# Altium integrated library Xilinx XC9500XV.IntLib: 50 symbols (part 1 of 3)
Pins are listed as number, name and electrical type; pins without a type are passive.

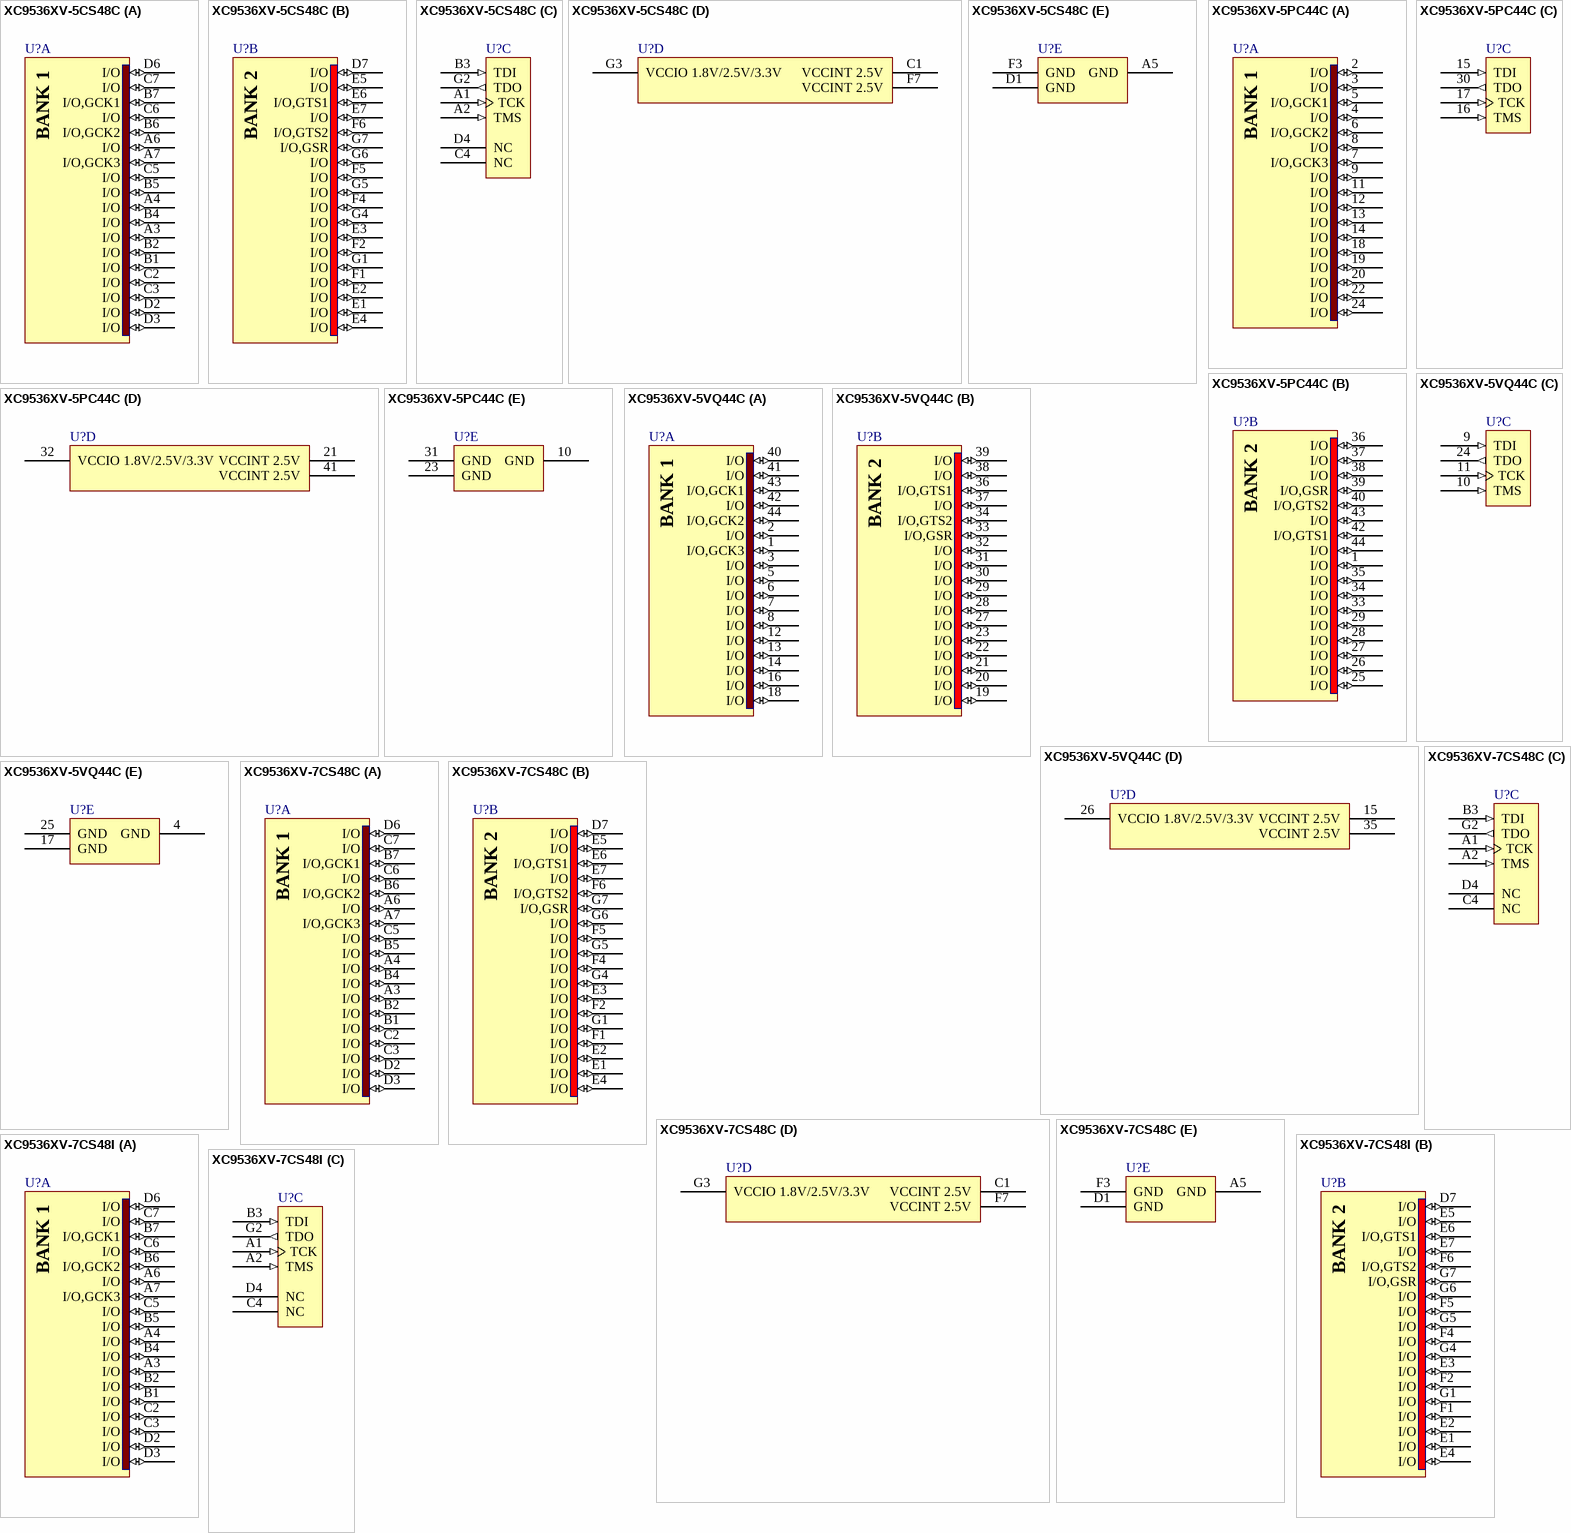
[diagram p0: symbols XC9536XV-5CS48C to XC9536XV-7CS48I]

## XC9536XV-5CS48C
designator U?
XC9500XV, 2.5V High-Performance CPLD with 36 Macrocells, 36 I/Os, 48-Ball CSBGA, Speed Grade 5, Commercial Grade
footprint CS48 (BGA, 48-Leads, Body 7x7mm, Pitch 0.8mm)
signal-integrity model XC9536XV_CS48 (XC9500XV)
part A pins: A3 I/O (io), A4 I/O (io), A6 I/O (io), A7 I/O,GCK3 (io), B1 I/O (io), B2 I/O (io), B4 I/O (io), B5 I/O (io), B6 I/O,GCK2 (io), B7 I/O,GCK1 (io), C2 I/O (io), C3 I/O (io), C5 I/O (io), C6 I/O (io), C7 I/O (io), D2 I/O (io), D3 I/O (io), D6 I/O (io)
part B pins: D7 I/O (io), E1 I/O (io), E2 I/O (io), E3 I/O (io), E4 I/O (io), E5 I/O (io), E6 I/O,GTS1 (io), E7 I/O (io), F1 I/O (io), F2 I/O (io), F4 I/O (io), F5 I/O (io), F6 I/O,GTS2 (io), G1 I/O (io), G4 I/O (io), G5 I/O (io), G6 I/O (io), G7 I/O,GSR (io)
part C pins: A1 TCK (in), A2 TMS (in), B3 TDI (in), C4 NC, D4 NC, G2 TDO (out)
part D pins: C1 VCCINT 2.5V (power), F7 VCCINT 2.5V (power), G3 VCCIO 1.8V/2.5V/3.3V (power)
part E pins: A5 GND (power), D1 GND (power), F3 GND (power)

## XC9536XV-5PC44C
designator U?
XC9500XV, 2.5V High-Performance CPLD with 36 Macrocells, 34 I/Os, 44-Pin PLCC, Speed Grade 5, Commercial Grade
footprint PC44_N (Leaded Chip Carrier, 44-Leads, Body 16.6x16.6mm, Pitch 1.27mm, IPC Medium Density)
footprint PC44_L (Leaded Chip Carrier, 44-Leads, Body 16.6x16.6mm, Pitch 1.27mm, IPC High Density)
footprint PC44_M (Leaded Chip Carrier, 44-Leads, Body 16.6x16.6mm, Pitch 1.27mm, IPC Low Density)
signal-integrity model XC9536XV_PLCC44 (XC9500XV)
part A pins: 2 I/O (io), 3 I/O (io), 4 I/O (io), 5 I/O,GCK1 (io), 6 I/O,GCK2 (io), 7 I/O,GCK3 (io), 8 I/O (io), 9 I/O (io), 11 I/O (io), 12 I/O (io), 13 I/O (io), 14 I/O (io), 18 I/O (io), 19 I/O (io), 20 I/O (io), 22 I/O (io), 24 I/O (io)
part B pins: 1 I/O (io), 25 I/O (io), 26 I/O (io), 27 I/O (io), 28 I/O (io), 29 I/O (io), 33 I/O (io), 34 I/O (io), 35 I/O (io), 36 I/O (io), 37 I/O (io), 38 I/O (io), 39 I/O,GSR (io), 40 I/O,GTS2 (io), 42 I/O,GTS1 (io), 43 I/O (io), 44 I/O (io)
part C pins: 15 TDI (in), 16 TMS (in), 17 TCK (in), 30 TDO (out)
part D pins: 21 VCCINT 2.5V (power), 32 VCCIO 1.8V/2.5V/3.3V (power), 41 VCCINT 2.5V (power)
part E pins: 10 GND (power), 23 GND (power), 31 GND (power)

## XC9536XV-5VQ44C
designator U?
XC9500XV, 2.5V High-Performance 36 Macrocell CPLD, 34 User I/Os, 44-Pin VQFP, Speed Grade 5, Commercial Grade
footprint VQ44_N (Thin QFP, 44-Leads, Body 10x10mm, Pitch 0.8mm, IPC Medium Density)
footprint VQ44_L (Thin QFP, 44-Leads, Body 10x10mm, Pitch 0.8mm, IPC High Density)
footprint VQ44_M (Thin QFP, 44-Leads, Body 10x10mm, Pitch 0.8mm, IPC Low Density)
signal-integrity model XC9536XV_VQ44 (XC9500XV)
part A pins: 1 I/O,GCK3 (io), 2 I/O (io), 3 I/O (io), 5 I/O (io), 6 I/O (io), 7 I/O (io), 8 I/O (io), 12 I/O (io), 13 I/O (io), 14 I/O (io), 16 I/O (io), 18 I/O (io), 40 I/O (io), 41 I/O (io), 42 I/O (io), 43 I/O,GCK1 (io), 44 I/O,GCK2 (io)
part B pins: 19 I/O (io), 20 I/O (io), 21 I/O (io), 22 I/O (io), 23 I/O (io), 27 I/O (io), 28 I/O (io), 29 I/O (io), 30 I/O (io), 31 I/O (io), 32 I/O (io), 33 I/O,GSR (io), 34 I/O,GTS2 (io), 36 I/O,GTS1 (io), 37 I/O (io), 38 I/O (io), 39 I/O (io)
part C pins: 9 TDI (in), 10 TMS (in), 11 TCK (in), 24 TDO (out)
part D pins: 15 VCCINT 2.5V (power), 26 VCCIO 1.8V/2.5V/3.3V (power), 35 VCCINT 2.5V (power)
part E pins: 4 GND (power), 17 GND (power), 25 GND (power)

## XC9536XV-7CS48C
designator U?
XC9500XV, 2.5V High-Performance CPLD with 36 Macrocells, 36 I/Os, 48-Ball CSBGA, Speed Grade 7, Commercial Grade
footprint CS48 (BGA, 48-Leads, Body 7x7mm, Pitch 0.8mm)
signal-integrity model XC9536XV_CS48 (XC9500XV)
part A pins: A3 I/O (io), A4 I/O (io), A6 I/O (io), A7 I/O,GCK3 (io), B1 I/O (io), B2 I/O (io), B4 I/O (io), B5 I/O (io), B6 I/O,GCK2 (io), B7 I/O,GCK1 (io), C2 I/O (io), C3 I/O (io), C5 I/O (io), C6 I/O (io), C7 I/O (io), D2 I/O (io), D3 I/O (io), D6 I/O (io)
part B pins: D7 I/O (io), E1 I/O (io), E2 I/O (io), E3 I/O (io), E4 I/O (io), E5 I/O (io), E6 I/O,GTS1 (io), E7 I/O (io), F1 I/O (io), F2 I/O (io), F4 I/O (io), F5 I/O (io), F6 I/O,GTS2 (io), G1 I/O (io), G4 I/O (io), G5 I/O (io), G6 I/O (io), G7 I/O,GSR (io)
part C pins: A1 TCK (in), A2 TMS (in), B3 TDI (in), C4 NC, D4 NC, G2 TDO (out)
part D pins: C1 VCCINT 2.5V (power), F7 VCCINT 2.5V (power), G3 VCCIO 1.8V/2.5V/3.3V (power)
part E pins: A5 GND (power), D1 GND (power), F3 GND (power)

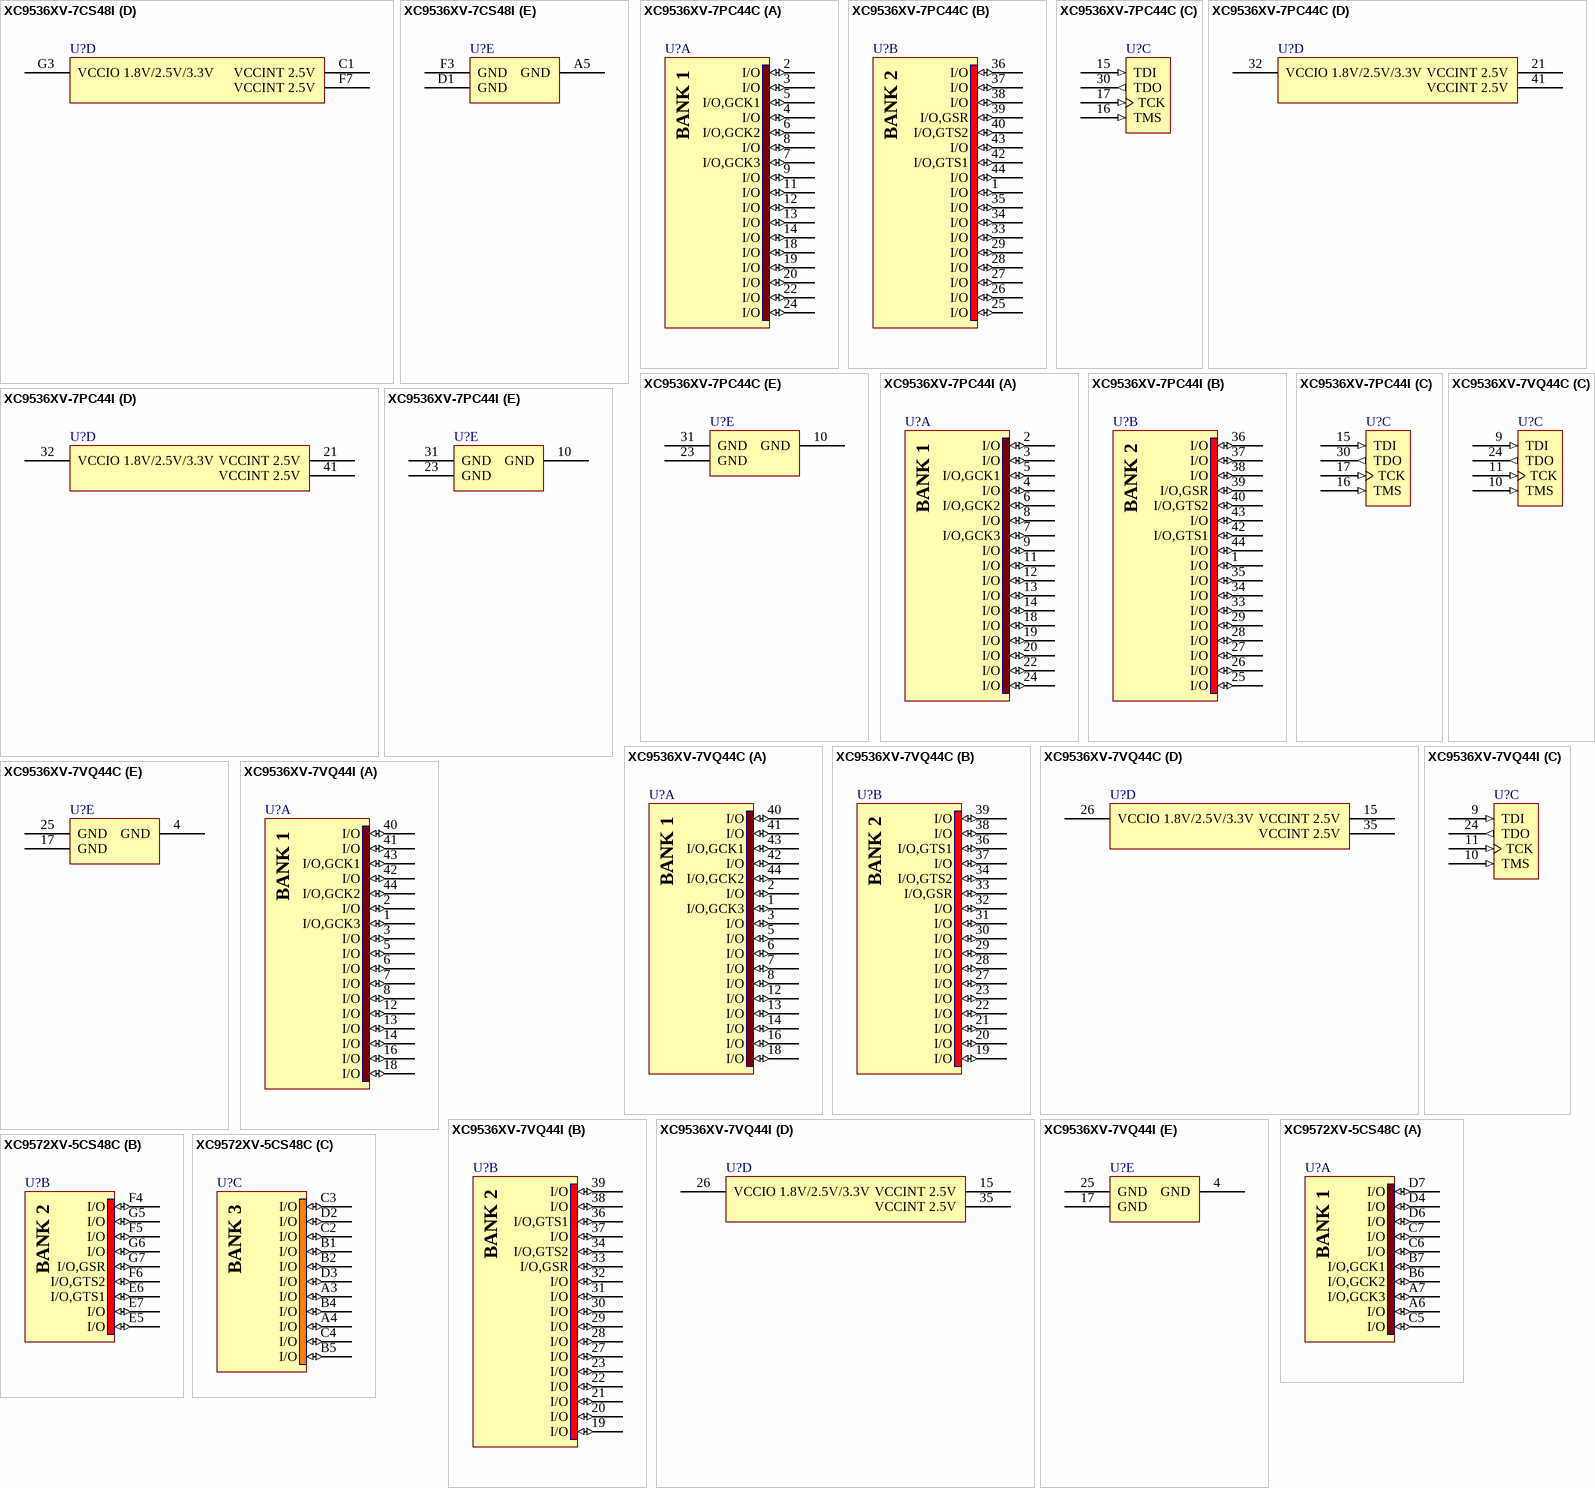
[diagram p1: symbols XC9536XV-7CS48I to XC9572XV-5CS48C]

## XC9536XV-7CS48I
designator U?
XC9500XV, 2.5V High-Performance CPLD with 36 Macrocells, 36 I/Os, 48-Ball CSBGA, Speed Grade 7, Industrial Grade
footprint CS48 (BGA, 48-Leads, Body 7x7mm, Pitch 0.8mm)
signal-integrity model XC9536XV_CS48 (XC9500XV)
part A pins: A3 I/O (io), A4 I/O (io), A6 I/O (io), A7 I/O,GCK3 (io), B1 I/O (io), B2 I/O (io), B4 I/O (io), B5 I/O (io), B6 I/O,GCK2 (io), B7 I/O,GCK1 (io), C2 I/O (io), C3 I/O (io), C5 I/O (io), C6 I/O (io), C7 I/O (io), D2 I/O (io), D3 I/O (io), D6 I/O (io)
part B pins: D7 I/O (io), E1 I/O (io), E2 I/O (io), E3 I/O (io), E4 I/O (io), E5 I/O (io), E6 I/O,GTS1 (io), E7 I/O (io), F1 I/O (io), F2 I/O (io), F4 I/O (io), F5 I/O (io), F6 I/O,GTS2 (io), G1 I/O (io), G4 I/O (io), G5 I/O (io), G6 I/O (io), G7 I/O,GSR (io)
part C pins: A1 TCK (in), A2 TMS (in), B3 TDI (in), C4 NC, D4 NC, G2 TDO (out)
part D pins: C1 VCCINT 2.5V (power), F7 VCCINT 2.5V (power), G3 VCCIO 1.8V/2.5V/3.3V (power)
part E pins: A5 GND (power), D1 GND (power), F3 GND (power)

## XC9536XV-7PC44C
designator U?
XC9500XV, 2.5V High-Performance CPLD with 36 Macrocells, 34 I/Os, 44-Pin PLCC, Speed Grade 7, Commercial Grade
footprint PC44_N (Leaded Chip Carrier, 44-Leads, Body 16.6x16.6mm, Pitch 1.27mm, IPC Medium Density)
footprint PC44_L (Leaded Chip Carrier, 44-Leads, Body 16.6x16.6mm, Pitch 1.27mm, IPC High Density)
footprint PC44_M (Leaded Chip Carrier, 44-Leads, Body 16.6x16.6mm, Pitch 1.27mm, IPC Low Density)
signal-integrity model XC9536XV_PLCC44 (XC9500XV)
part A pins: 2 I/O (io), 3 I/O (io), 4 I/O (io), 5 I/O,GCK1 (io), 6 I/O,GCK2 (io), 7 I/O,GCK3 (io), 8 I/O (io), 9 I/O (io), 11 I/O (io), 12 I/O (io), 13 I/O (io), 14 I/O (io), 18 I/O (io), 19 I/O (io), 20 I/O (io), 22 I/O (io), 24 I/O (io)
part B pins: 1 I/O (io), 25 I/O (io), 26 I/O (io), 27 I/O (io), 28 I/O (io), 29 I/O (io), 33 I/O (io), 34 I/O (io), 35 I/O (io), 36 I/O (io), 37 I/O (io), 38 I/O (io), 39 I/O,GSR (io), 40 I/O,GTS2 (io), 42 I/O,GTS1 (io), 43 I/O (io), 44 I/O (io)
part C pins: 15 TDI (in), 16 TMS (in), 17 TCK (in), 30 TDO (out)
part D pins: 21 VCCINT 2.5V (power), 32 VCCIO 1.8V/2.5V/3.3V (power), 41 VCCINT 2.5V (power)
part E pins: 10 GND (power), 23 GND (power), 31 GND (power)

## XC9536XV-7PC44I
designator U?
XC9500XV, 2.5V High-Performance CPLD with 36 Macrocells, 34 I/Os, 44-Pin PLCC, Speed Grade 7, Industrial Grade
footprint PC44_N (Leaded Chip Carrier, 44-Leads, Body 16.6x16.6mm, Pitch 1.27mm, IPC Medium Density)
footprint PC44_L (Leaded Chip Carrier, 44-Leads, Body 16.6x16.6mm, Pitch 1.27mm, IPC High Density)
footprint PC44_M (Leaded Chip Carrier, 44-Leads, Body 16.6x16.6mm, Pitch 1.27mm, IPC Low Density)
signal-integrity model XC9536XV_PLCC44 (XC9500XV)
part A pins: 2 I/O (io), 3 I/O (io), 4 I/O (io), 5 I/O,GCK1 (io), 6 I/O,GCK2 (io), 7 I/O,GCK3 (io), 8 I/O (io), 9 I/O (io), 11 I/O (io), 12 I/O (io), 13 I/O (io), 14 I/O (io), 18 I/O (io), 19 I/O (io), 20 I/O (io), 22 I/O (io), 24 I/O (io)
part B pins: 1 I/O (io), 25 I/O (io), 26 I/O (io), 27 I/O (io), 28 I/O (io), 29 I/O (io), 33 I/O (io), 34 I/O (io), 35 I/O (io), 36 I/O (io), 37 I/O (io), 38 I/O (io), 39 I/O,GSR (io), 40 I/O,GTS2 (io), 42 I/O,GTS1 (io), 43 I/O (io), 44 I/O (io)
part C pins: 15 TDI (in), 16 TMS (in), 17 TCK (in), 30 TDO (out)
part D pins: 21 VCCINT 2.5V (power), 32 VCCIO 1.8V/2.5V/3.3V (power), 41 VCCINT 2.5V (power)
part E pins: 10 GND (power), 23 GND (power), 31 GND (power)

## XC9536XV-7VQ44C
designator U?
XC9500XV, 2.5V High-Performance 36 Macrocell CPLD, 34 User I/Os, 44-Pin VQFP, Speed Grade 7, Commercial Grade
footprint VQ44_N (Thin QFP, 44-Leads, Body 10x10mm, Pitch 0.8mm, IPC Medium Density)
footprint VQ44_L (Thin QFP, 44-Leads, Body 10x10mm, Pitch 0.8mm, IPC High Density)
footprint VQ44_M (Thin QFP, 44-Leads, Body 10x10mm, Pitch 0.8mm, IPC Low Density)
signal-integrity model XC9536XV_VQ44 (XC9500XV)
part A pins: 1 I/O,GCK3 (io), 2 I/O (io), 3 I/O (io), 5 I/O (io), 6 I/O (io), 7 I/O (io), 8 I/O (io), 12 I/O (io), 13 I/O (io), 14 I/O (io), 16 I/O (io), 18 I/O (io), 40 I/O (io), 41 I/O (io), 42 I/O (io), 43 I/O,GCK1 (io), 44 I/O,GCK2 (io)
part B pins: 19 I/O (io), 20 I/O (io), 21 I/O (io), 22 I/O (io), 23 I/O (io), 27 I/O (io), 28 I/O (io), 29 I/O (io), 30 I/O (io), 31 I/O (io), 32 I/O (io), 33 I/O,GSR (io), 34 I/O,GTS2 (io), 36 I/O,GTS1 (io), 37 I/O (io), 38 I/O (io), 39 I/O (io)
part C pins: 9 TDI (in), 10 TMS (in), 11 TCK (in), 24 TDO (out)
part D pins: 15 VCCINT 2.5V (power), 26 VCCIO 1.8V/2.5V/3.3V (power), 35 VCCINT 2.5V (power)
part E pins: 4 GND (power), 17 GND (power), 25 GND (power)

## XC9536XV-7VQ44I
designator U?
XC9500XV, 2.5V High-Performance 36 Macrocell CPLD, 34 User I/Os, 44-Pin VQFP, Speed Grade 7, Industrial Grade
footprint VQ44_N (Thin QFP, 44-Leads, Body 10x10mm, Pitch 0.8mm, IPC Medium Density)
footprint VQ44_L (Thin QFP, 44-Leads, Body 10x10mm, Pitch 0.8mm, IPC High Density)
footprint VQ44_M (Thin QFP, 44-Leads, Body 10x10mm, Pitch 0.8mm, IPC Low Density)
signal-integrity model XC9536XV_VQ44 (XC9500XV)
part A pins: 1 I/O,GCK3 (io), 2 I/O (io), 3 I/O (io), 5 I/O (io), 6 I/O (io), 7 I/O (io), 8 I/O (io), 12 I/O (io), 13 I/O (io), 14 I/O (io), 16 I/O (io), 18 I/O (io), 40 I/O (io), 41 I/O (io), 42 I/O (io), 43 I/O,GCK1 (io), 44 I/O,GCK2 (io)
part B pins: 19 I/O (io), 20 I/O (io), 21 I/O (io), 22 I/O (io), 23 I/O (io), 27 I/O (io), 28 I/O (io), 29 I/O (io), 30 I/O (io), 31 I/O (io), 32 I/O (io), 33 I/O,GSR (io), 34 I/O,GTS2 (io), 36 I/O,GTS1 (io), 37 I/O (io), 38 I/O (io), 39 I/O (io)
part C pins: 9 TDI (in), 10 TMS (in), 11 TCK (in), 24 TDO (out)
part D pins: 15 VCCINT 2.5V (power), 26 VCCIO 1.8V/2.5V/3.3V (power), 35 VCCINT 2.5V (power)
part E pins: 4 GND (power), 17 GND (power), 25 GND (power)

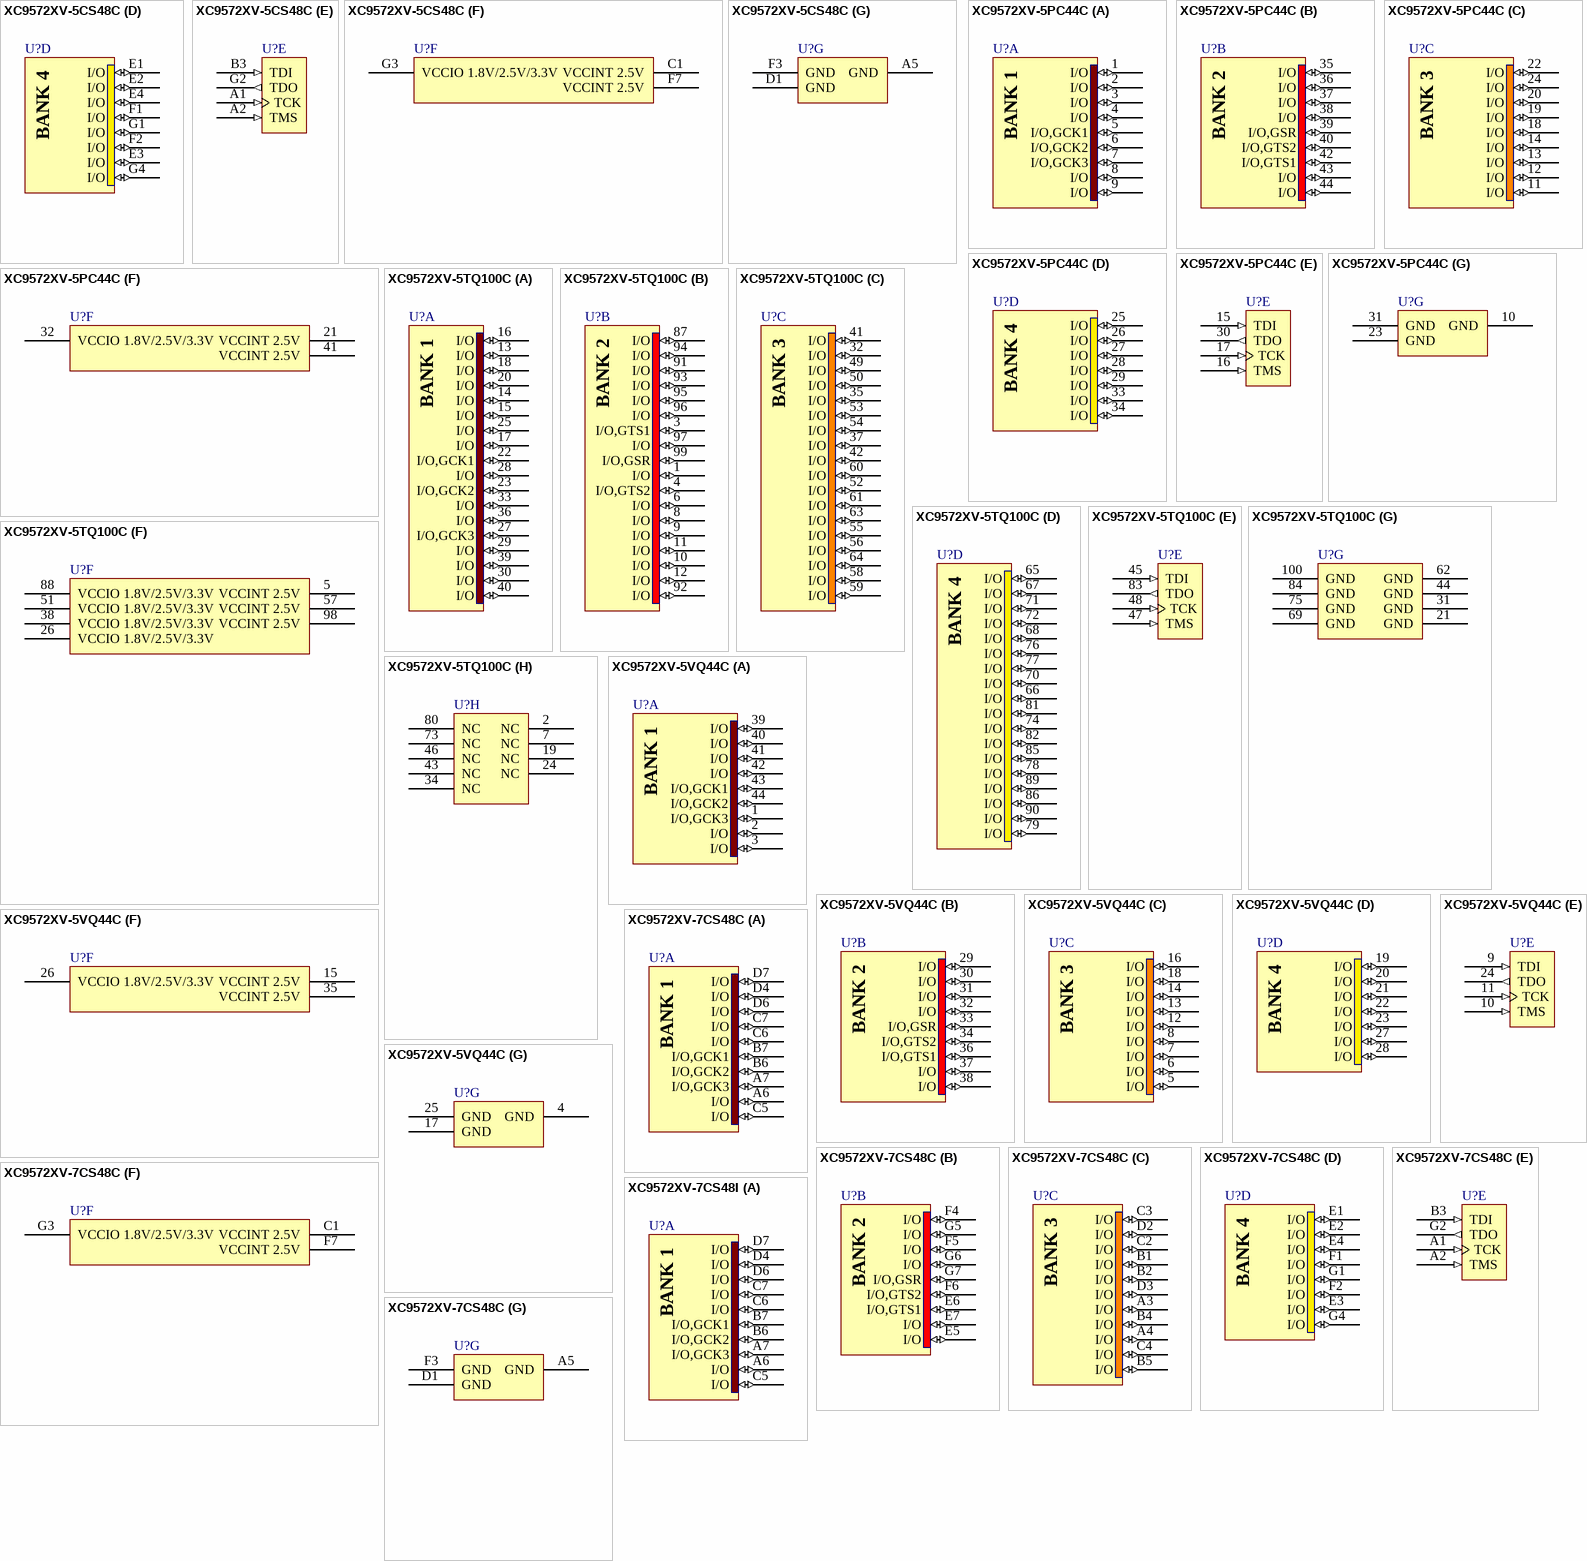
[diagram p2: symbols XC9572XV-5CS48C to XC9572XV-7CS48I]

## XC9572XV-5CS48C
designator U?
XC9500XV, 2.5V High-Performance CPLD with 72 Macrocells, 38 I/Os, 48-Ball CSBGA, Speed Grade 5, Commercial Grade
footprint CS48 (BGA, 48-Leads, Body 7x7mm, Pitch 0.8mm)
signal-integrity model XC9572XV_CS48 (XC9500XV)
part A pins: A6 I/O (io), A7 I/O,GCK3 (io), B6 I/O,GCK2 (io), B7 I/O,GCK1 (io), C5 I/O (io), C6 I/O (io), C7 I/O (io), D4 I/O (io), D6 I/O (io), D7 I/O (io)
part B pins: E5 I/O (io), E6 I/O,GTS1 (io), E7 I/O (io), F4 I/O (io), F5 I/O (io), F6 I/O,GTS2 (io), G5 I/O (io), G6 I/O (io), G7 I/O,GSR (io)
part C pins: A3 I/O (io), A4 I/O (io), B1 I/O (io), B2 I/O (io), B4 I/O (io), B5 I/O (io), C2 I/O (io), C3 I/O (io), C4 I/O (io), D2 I/O (io), D3 I/O (io)
part D pins: E1 I/O (io), E2 I/O (io), E3 I/O (io), E4 I/O (io), F1 I/O (io), F2 I/O (io), G1 I/O (io), G4 I/O (io)
part E pins: A1 TCK (in), A2 TMS (in), B3 TDI (in), G2 TDO (out)
part F pins: C1 VCCINT 2.5V (power), F7 VCCINT 2.5V (power), G3 VCCIO 1.8V/2.5V/3.3V (power)
part G pins: A5 GND (power), D1 GND (power), F3 GND (power)

## XC9572XV-5PC44C
designator U?
XC9500XV, 2.5V High-Performance CPLD with 72 Macrocells, 34 I/Os, 44-Pin PLCC, Speed Grade 5, Commercial Grade
footprint PC44_N (Leaded Chip Carrier, 44-Leads, Body 16.6x16.6mm, Pitch 1.27mm, IPC Medium Density)
footprint PC44_L (Leaded Chip Carrier, 44-Leads, Body 16.6x16.6mm, Pitch 1.27mm, IPC High Density)
footprint PC44_M (Leaded Chip Carrier, 44-Leads, Body 16.6x16.6mm, Pitch 1.27mm, IPC Low Density)
signal-integrity model XC9572XV_PLCC44 (XC9500XV)
part A pins: 1 I/O (io), 2 I/O (io), 3 I/O (io), 4 I/O (io), 5 I/O,GCK1 (io), 6 I/O,GCK2 (io), 7 I/O,GCK3 (io), 8 I/O (io), 9 I/O (io)
part B pins: 35 I/O (io), 36 I/O (io), 37 I/O (io), 38 I/O (io), 39 I/O,GSR (io), 40 I/O,GTS2 (io), 42 I/O,GTS1 (io), 43 I/O (io), 44 I/O (io)
part C pins: 11 I/O (io), 12 I/O (io), 13 I/O (io), 14 I/O (io), 18 I/O (io), 19 I/O (io), 20 I/O (io), 22 I/O (io), 24 I/O (io)
part D pins: 25 I/O (io), 26 I/O (io), 27 I/O (io), 28 I/O (io), 29 I/O (io), 33 I/O (io), 34 I/O (io)
part E pins: 15 TDI (in), 16 TMS (in), 17 TCK (in), 30 TDO (out)
part F pins: 21 VCCINT 2.5V (power), 32 VCCIO 1.8V/2.5V/3.3V (power), 41 VCCINT 2.5V (power)
part G pins: 10 GND (power), 23 GND (power), 31 GND (power)

## XC9572XV-5TQ100C
designator U?
XC9500XV, 2.5V High-Performance 72 Macrocell CPLD, 72 User I/Os, 100-Pin TQFP, Speed Grade 5, Commercial Grade
footprint TQ100_N (Thin QFP, 100-Leads, Body 14x14mm, Pitch 0.5mm, IPC Medium Density)
footprint TQ100_L (Thin QFP, 100-Leads, Body 14x14mm, Pitch 0.5mm, IPC High Density)
footprint TQ100_M (Thin QFP, 100-Leads, Body 14x14mm, Pitch 0.5mm, IPC Low Density)
signal-integrity model XC9572XV_TQ100 (XC9500XV)
part A pins: 13 I/O (io), 14 I/O (io), 15 I/O (io), 16 I/O (io), 17 I/O (io), 18 I/O (io), 20 I/O (io), 22 I/O,GCK1 (io), 23 I/O,GCK2 (io), 25 I/O (io), 27 I/O,GCK3 (io), 28 I/O (io), 29 I/O (io), 30 I/O (io), 33 I/O (io), 36 I/O (io), 39 I/O (io), 40 I/O (io)
part B pins: 1 I/O (io), 3 I/O,GTS1 (io), 4 I/O,GTS2 (io), 6 I/O (io), 8 I/O (io), 9 I/O (io), 10 I/O (io), 11 I/O (io), 12 I/O (io), 87 I/O (io), 91 I/O (io), 92 I/O (io), 93 I/O (io), 94 I/O (io), 95 I/O (io), 96 I/O (io), 97 I/O (io), 99 I/O,GSR (io)
part C pins: 32 I/O (io), 35 I/O (io), 37 I/O (io), 41 I/O (io), 42 I/O (io), 49 I/O (io), 50 I/O (io), 52 I/O (io), 53 I/O (io), 54 I/O (io), 55 I/O (io), 56 I/O (io), 58 I/O (io), 59 I/O (io), 60 I/O (io), 61 I/O (io), 63 I/O (io), 64 I/O (io)
part D pins: 65 I/O (io), 66 I/O (io), 67 I/O (io), 68 I/O (io), 70 I/O (io), 71 I/O (io), 72 I/O (io), 74 I/O (io), 76 I/O (io), 77 I/O (io), 78 I/O (io), 79 I/O (io), 81 I/O (io), 82 I/O (io), 85 I/O (io), 86 I/O (io), 89 I/O (io), 90 I/O (io)
part E pins: 45 TDI (in), 47 TMS (in), 48 TCK (in), 83 TDO (out)
part F pins: 5 VCCINT 2.5V (power), 26 VCCIO 1.8V/2.5V/3.3V (power), 38 VCCIO 1.8V/2.5V/3.3V (power), 51 VCCIO 1.8V/2.5V/3.3V (power), 57 VCCINT 2.5V (power), 88 VCCIO 1.8V/2.5V/3.3V (power), 98 VCCINT 2.5V (power)
part G pins: 21 GND (power), 31 GND (power), 44 GND (power), 62 GND (power), 69 GND (power), 75 GND (power), 84 GND (power), 100 GND (power)
part H pins: 2 NC, 7 NC, 19 NC, 24 NC, 34 NC, 43 NC, 46 NC, 73 NC, 80 NC

## XC9572XV-5VQ44C
designator U?
XC9500XV, 2.5V High-Performance 72 Macrocell CPLD, 34 User I/Os, 44-Pin VQFP, Speed Grade 5, Commercial Grade
footprint VQ44_N (Thin QFP, 44-Leads, Body 10x10mm, Pitch 0.8mm, IPC Medium Density)
footprint VQ44_L (Thin QFP, 44-Leads, Body 10x10mm, Pitch 0.8mm, IPC High Density)
footprint VQ44_M (Thin QFP, 44-Leads, Body 10x10mm, Pitch 0.8mm, IPC Low Density)
signal-integrity model XC9572XV_VQ44 (XC9500XV)
part A pins: 1 I/O,GCK3 (io), 2 I/O (io), 3 I/O (io), 39 I/O (io), 40 I/O (io), 41 I/O (io), 42 I/O (io), 43 I/O,GCK1 (io), 44 I/O,GCK2 (io)
part B pins: 29 I/O (io), 30 I/O (io), 31 I/O (io), 32 I/O (io), 33 I/O,GSR (io), 34 I/O,GTS2 (io), 36 I/O,GTS1 (io), 37 I/O (io), 38 I/O (io)
part C pins: 5 I/O (io), 6 I/O (io), 7 I/O (io), 8 I/O (io), 12 I/O (io), 13 I/O (io), 14 I/O (io), 16 I/O (io), 18 I/O (io)
part D pins: 19 I/O (io), 20 I/O (io), 21 I/O (io), 22 I/O (io), 23 I/O (io), 27 I/O (io), 28 I/O (io)
part E pins: 9 TDI (in), 10 TMS (in), 11 TCK (in), 24 TDO (out)
part F pins: 15 VCCINT 2.5V (power), 26 VCCIO 1.8V/2.5V/3.3V (power), 35 VCCINT 2.5V (power)
part G pins: 4 GND (power), 17 GND (power), 25 GND (power)

## XC9572XV-7CS48C
designator U?
XC9500XV, 2.5V High-Performance CPLD with 72 Macrocells, 38 I/Os, 48-Ball CSBGA, Speed Grade 7, Commercial Grade
footprint CS48 (BGA, 48-Leads, Body 7x7mm, Pitch 0.8mm)
signal-integrity model XC9572XV_CS48 (XC9500XV)
part A pins: A6 I/O (io), A7 I/O,GCK3 (io), B6 I/O,GCK2 (io), B7 I/O,GCK1 (io), C5 I/O (io), C6 I/O (io), C7 I/O (io), D4 I/O (io), D6 I/O (io), D7 I/O (io)
part B pins: E5 I/O (io), E6 I/O,GTS1 (io), E7 I/O (io), F4 I/O (io), F5 I/O (io), F6 I/O,GTS2 (io), G5 I/O (io), G6 I/O (io), G7 I/O,GSR (io)
part C pins: A3 I/O (io), A4 I/O (io), B1 I/O (io), B2 I/O (io), B4 I/O (io), B5 I/O (io), C2 I/O (io), C3 I/O (io), C4 I/O (io), D2 I/O (io), D3 I/O (io)
part D pins: E1 I/O (io), E2 I/O (io), E3 I/O (io), E4 I/O (io), F1 I/O (io), F2 I/O (io), G1 I/O (io), G4 I/O (io)
part E pins: A1 TCK (in), A2 TMS (in), B3 TDI (in), G2 TDO (out)
part F pins: C1 VCCINT 2.5V (power), F7 VCCINT 2.5V (power), G3 VCCIO 1.8V/2.5V/3.3V (power)
part G pins: A5 GND (power), D1 GND (power), F3 GND (power)

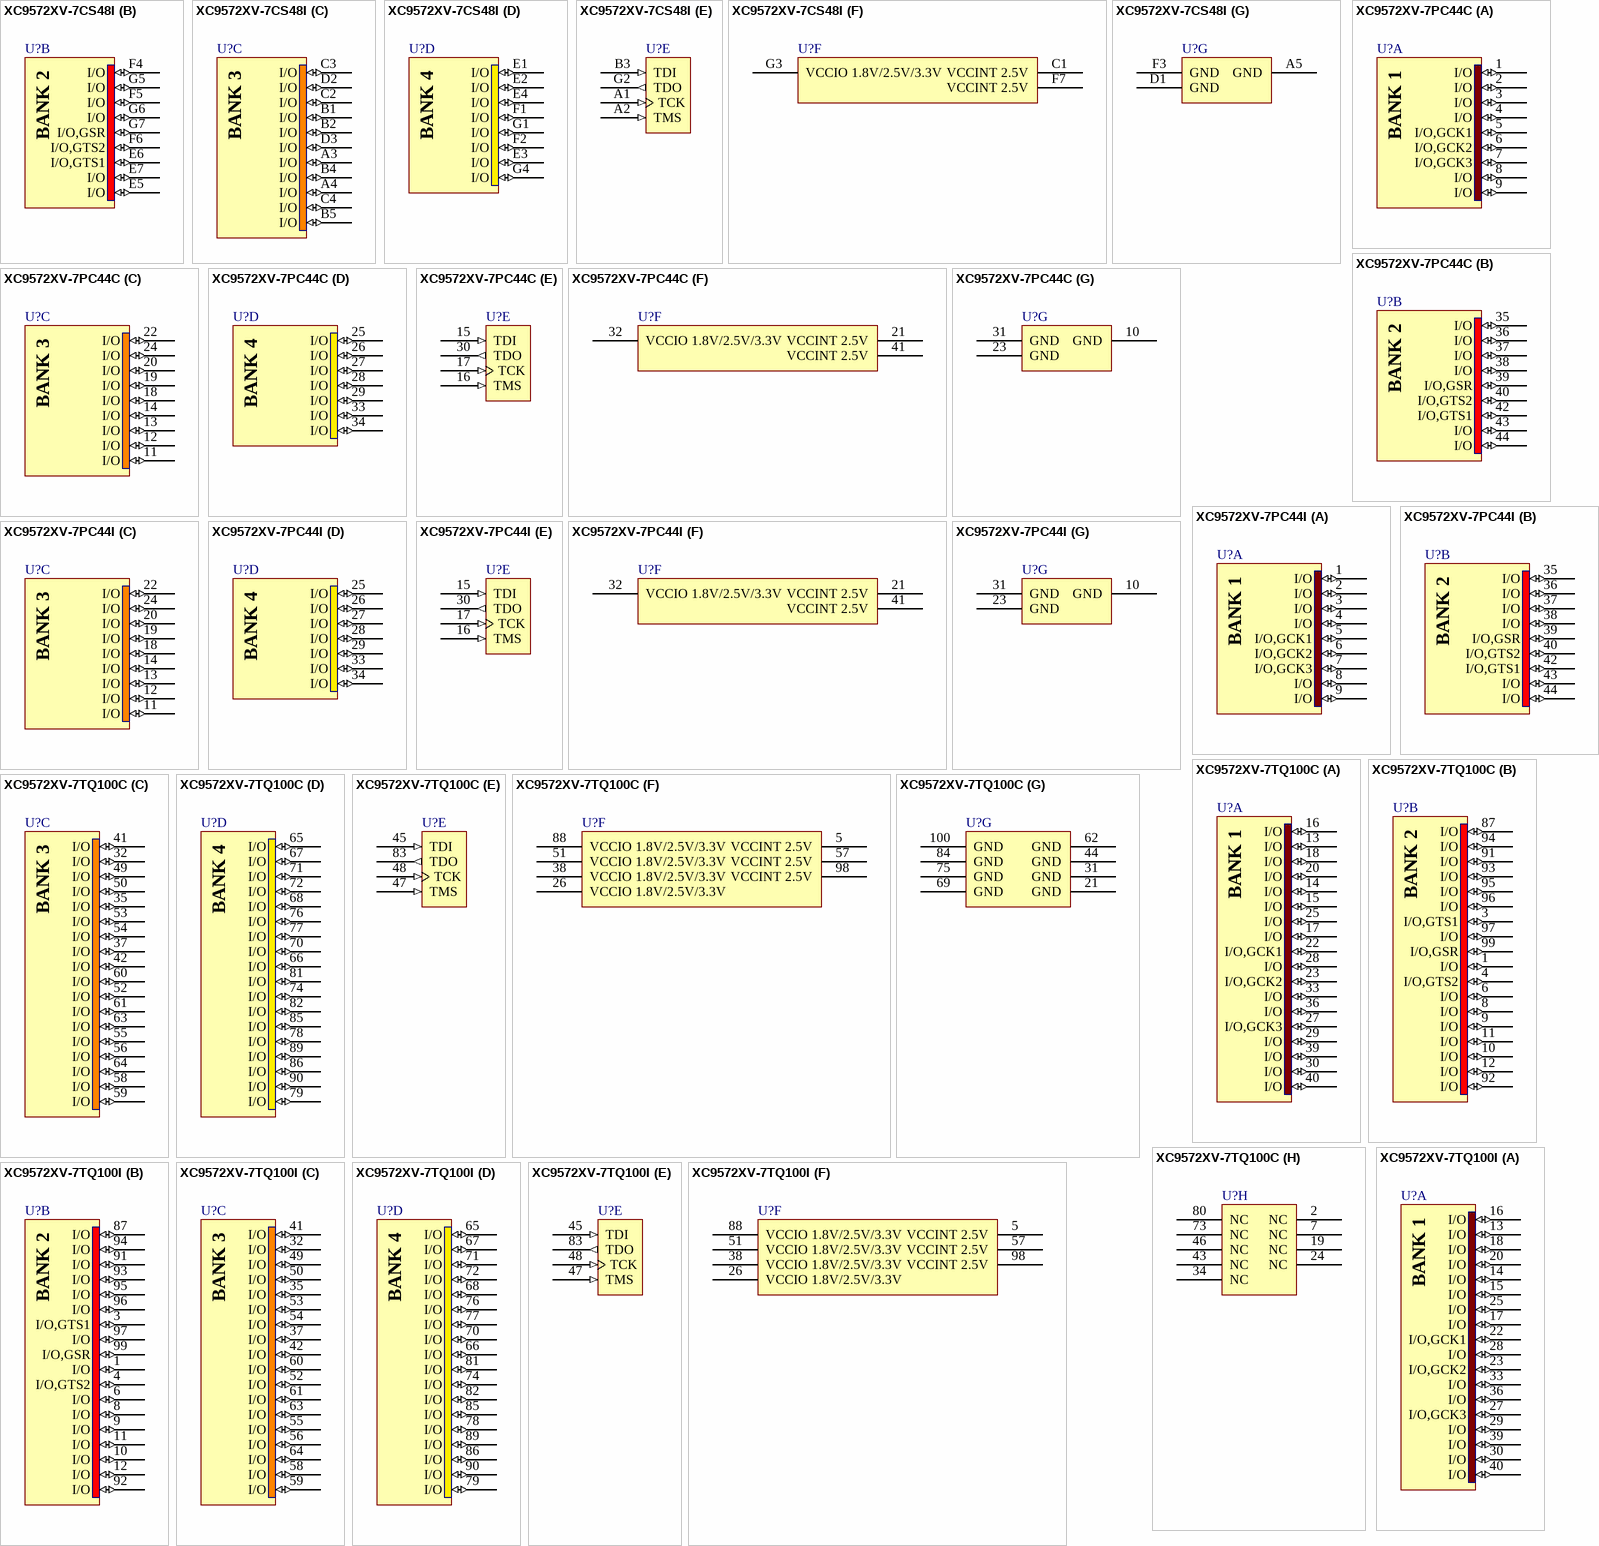
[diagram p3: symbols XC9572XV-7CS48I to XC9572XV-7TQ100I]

## XC9572XV-7CS48I
designator U?
XC9500XV, 2.5V High-Performance CPLD with 72 Macrocells, 38 I/Os, 48-Ball CSBGA, Speed Grade 7, Industrial Grade
footprint CS48 (BGA, 48-Leads, Body 7x7mm, Pitch 0.8mm)
signal-integrity model XC9572XV_CS48 (XC9500XV)
part A pins: A6 I/O (io), A7 I/O,GCK3 (io), B6 I/O,GCK2 (io), B7 I/O,GCK1 (io), C5 I/O (io), C6 I/O (io), C7 I/O (io), D4 I/O (io), D6 I/O (io), D7 I/O (io)
part B pins: E5 I/O (io), E6 I/O,GTS1 (io), E7 I/O (io), F4 I/O (io), F5 I/O (io), F6 I/O,GTS2 (io), G5 I/O (io), G6 I/O (io), G7 I/O,GSR (io)
part C pins: A3 I/O (io), A4 I/O (io), B1 I/O (io), B2 I/O (io), B4 I/O (io), B5 I/O (io), C2 I/O (io), C3 I/O (io), C4 I/O (io), D2 I/O (io), D3 I/O (io)
part D pins: E1 I/O (io), E2 I/O (io), E3 I/O (io), E4 I/O (io), F1 I/O (io), F2 I/O (io), G1 I/O (io), G4 I/O (io)
part E pins: A1 TCK (in), A2 TMS (in), B3 TDI (in), G2 TDO (out)
part F pins: C1 VCCINT 2.5V (power), F7 VCCINT 2.5V (power), G3 VCCIO 1.8V/2.5V/3.3V (power)
part G pins: A5 GND (power), D1 GND (power), F3 GND (power)

## XC9572XV-7PC44C
designator U?
XC9500XV, 2.5V High-Performance CPLD with 72 Macrocells, 34 I/Os, 44-Pin PLCC, Speed Grade 7, Commercial Grade
footprint PC44_N (Leaded Chip Carrier, 44-Leads, Body 16.6x16.6mm, Pitch 1.27mm, IPC Medium Density)
footprint PC44_L (Leaded Chip Carrier, 44-Leads, Body 16.6x16.6mm, Pitch 1.27mm, IPC High Density)
footprint PC44_M (Leaded Chip Carrier, 44-Leads, Body 16.6x16.6mm, Pitch 1.27mm, IPC Low Density)
signal-integrity model XC9572XV_PLCC44 (XC9500XV)
part A pins: 1 I/O (io), 2 I/O (io), 3 I/O (io), 4 I/O (io), 5 I/O,GCK1 (io), 6 I/O,GCK2 (io), 7 I/O,GCK3 (io), 8 I/O (io), 9 I/O (io)
part B pins: 35 I/O (io), 36 I/O (io), 37 I/O (io), 38 I/O (io), 39 I/O,GSR (io), 40 I/O,GTS2 (io), 42 I/O,GTS1 (io), 43 I/O (io), 44 I/O (io)
part C pins: 11 I/O (io), 12 I/O (io), 13 I/O (io), 14 I/O (io), 18 I/O (io), 19 I/O (io), 20 I/O (io), 22 I/O (io), 24 I/O (io)
part D pins: 25 I/O (io), 26 I/O (io), 27 I/O (io), 28 I/O (io), 29 I/O (io), 33 I/O (io), 34 I/O (io)
part E pins: 15 TDI (in), 16 TMS (in), 17 TCK (in), 30 TDO (out)
part F pins: 21 VCCINT 2.5V (power), 32 VCCIO 1.8V/2.5V/3.3V (power), 41 VCCINT 2.5V (power)
part G pins: 10 GND (power), 23 GND (power), 31 GND (power)

## XC9572XV-7PC44I
designator U?
XC9500XV, 2.5V High-Performance CPLD with 72 Macrocells, 34 I/Os, 44-Pin PLCC, Speed Grade 7, Industrial Grade
footprint PC44_N (Leaded Chip Carrier, 44-Leads, Body 16.6x16.6mm, Pitch 1.27mm, IPC Medium Density)
footprint PC44_L (Leaded Chip Carrier, 44-Leads, Body 16.6x16.6mm, Pitch 1.27mm, IPC High Density)
footprint PC44_M (Leaded Chip Carrier, 44-Leads, Body 16.6x16.6mm, Pitch 1.27mm, IPC Low Density)
signal-integrity model XC9572XV_PLCC44 (XC9500XV)
part A pins: 1 I/O (io), 2 I/O (io), 3 I/O (io), 4 I/O (io), 5 I/O,GCK1 (io), 6 I/O,GCK2 (io), 7 I/O,GCK3 (io), 8 I/O (io), 9 I/O (io)
part B pins: 35 I/O (io), 36 I/O (io), 37 I/O (io), 38 I/O (io), 39 I/O,GSR (io), 40 I/O,GTS2 (io), 42 I/O,GTS1 (io), 43 I/O (io), 44 I/O (io)
part C pins: 11 I/O (io), 12 I/O (io), 13 I/O (io), 14 I/O (io), 18 I/O (io), 19 I/O (io), 20 I/O (io), 22 I/O (io), 24 I/O (io)
part D pins: 25 I/O (io), 26 I/O (io), 27 I/O (io), 28 I/O (io), 29 I/O (io), 33 I/O (io), 34 I/O (io)
part E pins: 15 TDI (in), 16 TMS (in), 17 TCK (in), 30 TDO (out)
part F pins: 21 VCCINT 2.5V (power), 32 VCCIO 1.8V/2.5V/3.3V (power), 41 VCCINT 2.5V (power)
part G pins: 10 GND (power), 23 GND (power), 31 GND (power)

## XC9572XV-7TQ100C
designator U?
XC9500XV, 2.5V High-Performance 72 Macrocell CPLD, 72 User I/Os, 100-Pin TQFP, Speed Grade 7, Commercial Grade
footprint TQ100_N (Thin QFP, 100-Leads, Body 14x14mm, Pitch 0.5mm, IPC Medium Density)
footprint TQ100_L (Thin QFP, 100-Leads, Body 14x14mm, Pitch 0.5mm, IPC High Density)
footprint TQ100_M (Thin QFP, 100-Leads, Body 14x14mm, Pitch 0.5mm, IPC Low Density)
signal-integrity model XC9572XV_TQ100 (XC9500XV)
part A pins: 13 I/O (io), 14 I/O (io), 15 I/O (io), 16 I/O (io), 17 I/O (io), 18 I/O (io), 20 I/O (io), 22 I/O,GCK1 (io), 23 I/O,GCK2 (io), 25 I/O (io), 27 I/O,GCK3 (io), 28 I/O (io), 29 I/O (io), 30 I/O (io), 33 I/O (io), 36 I/O (io), 39 I/O (io), 40 I/O (io)
part B pins: 1 I/O (io), 3 I/O,GTS1 (io), 4 I/O,GTS2 (io), 6 I/O (io), 8 I/O (io), 9 I/O (io), 10 I/O (io), 11 I/O (io), 12 I/O (io), 87 I/O (io), 91 I/O (io), 92 I/O (io), 93 I/O (io), 94 I/O (io), 95 I/O (io), 96 I/O (io), 97 I/O (io), 99 I/O,GSR (io)
part C pins: 32 I/O (io), 35 I/O (io), 37 I/O (io), 41 I/O (io), 42 I/O (io), 49 I/O (io), 50 I/O (io), 52 I/O (io), 53 I/O (io), 54 I/O (io), 55 I/O (io), 56 I/O (io), 58 I/O (io), 59 I/O (io), 60 I/O (io), 61 I/O (io), 63 I/O (io), 64 I/O (io)
part D pins: 65 I/O (io), 66 I/O (io), 67 I/O (io), 68 I/O (io), 70 I/O (io), 71 I/O (io), 72 I/O (io), 74 I/O (io), 76 I/O (io), 77 I/O (io), 78 I/O (io), 79 I/O (io), 81 I/O (io), 82 I/O (io), 85 I/O (io), 86 I/O (io), 89 I/O (io), 90 I/O (io)
part E pins: 45 TDI (in), 47 TMS (in), 48 TCK (in), 83 TDO (out)
part F pins: 5 VCCINT 2.5V (power), 26 VCCIO 1.8V/2.5V/3.3V (power), 38 VCCIO 1.8V/2.5V/3.3V (power), 51 VCCIO 1.8V/2.5V/3.3V (power), 57 VCCINT 2.5V (power), 88 VCCIO 1.8V/2.5V/3.3V (power), 98 VCCINT 2.5V (power)
part G pins: 21 GND (power), 31 GND (power), 44 GND (power), 62 GND (power), 69 GND (power), 75 GND (power), 84 GND (power), 100 GND (power)
part H pins: 2 NC, 7 NC, 19 NC, 24 NC, 34 NC, 43 NC, 46 NC, 73 NC, 80 NC

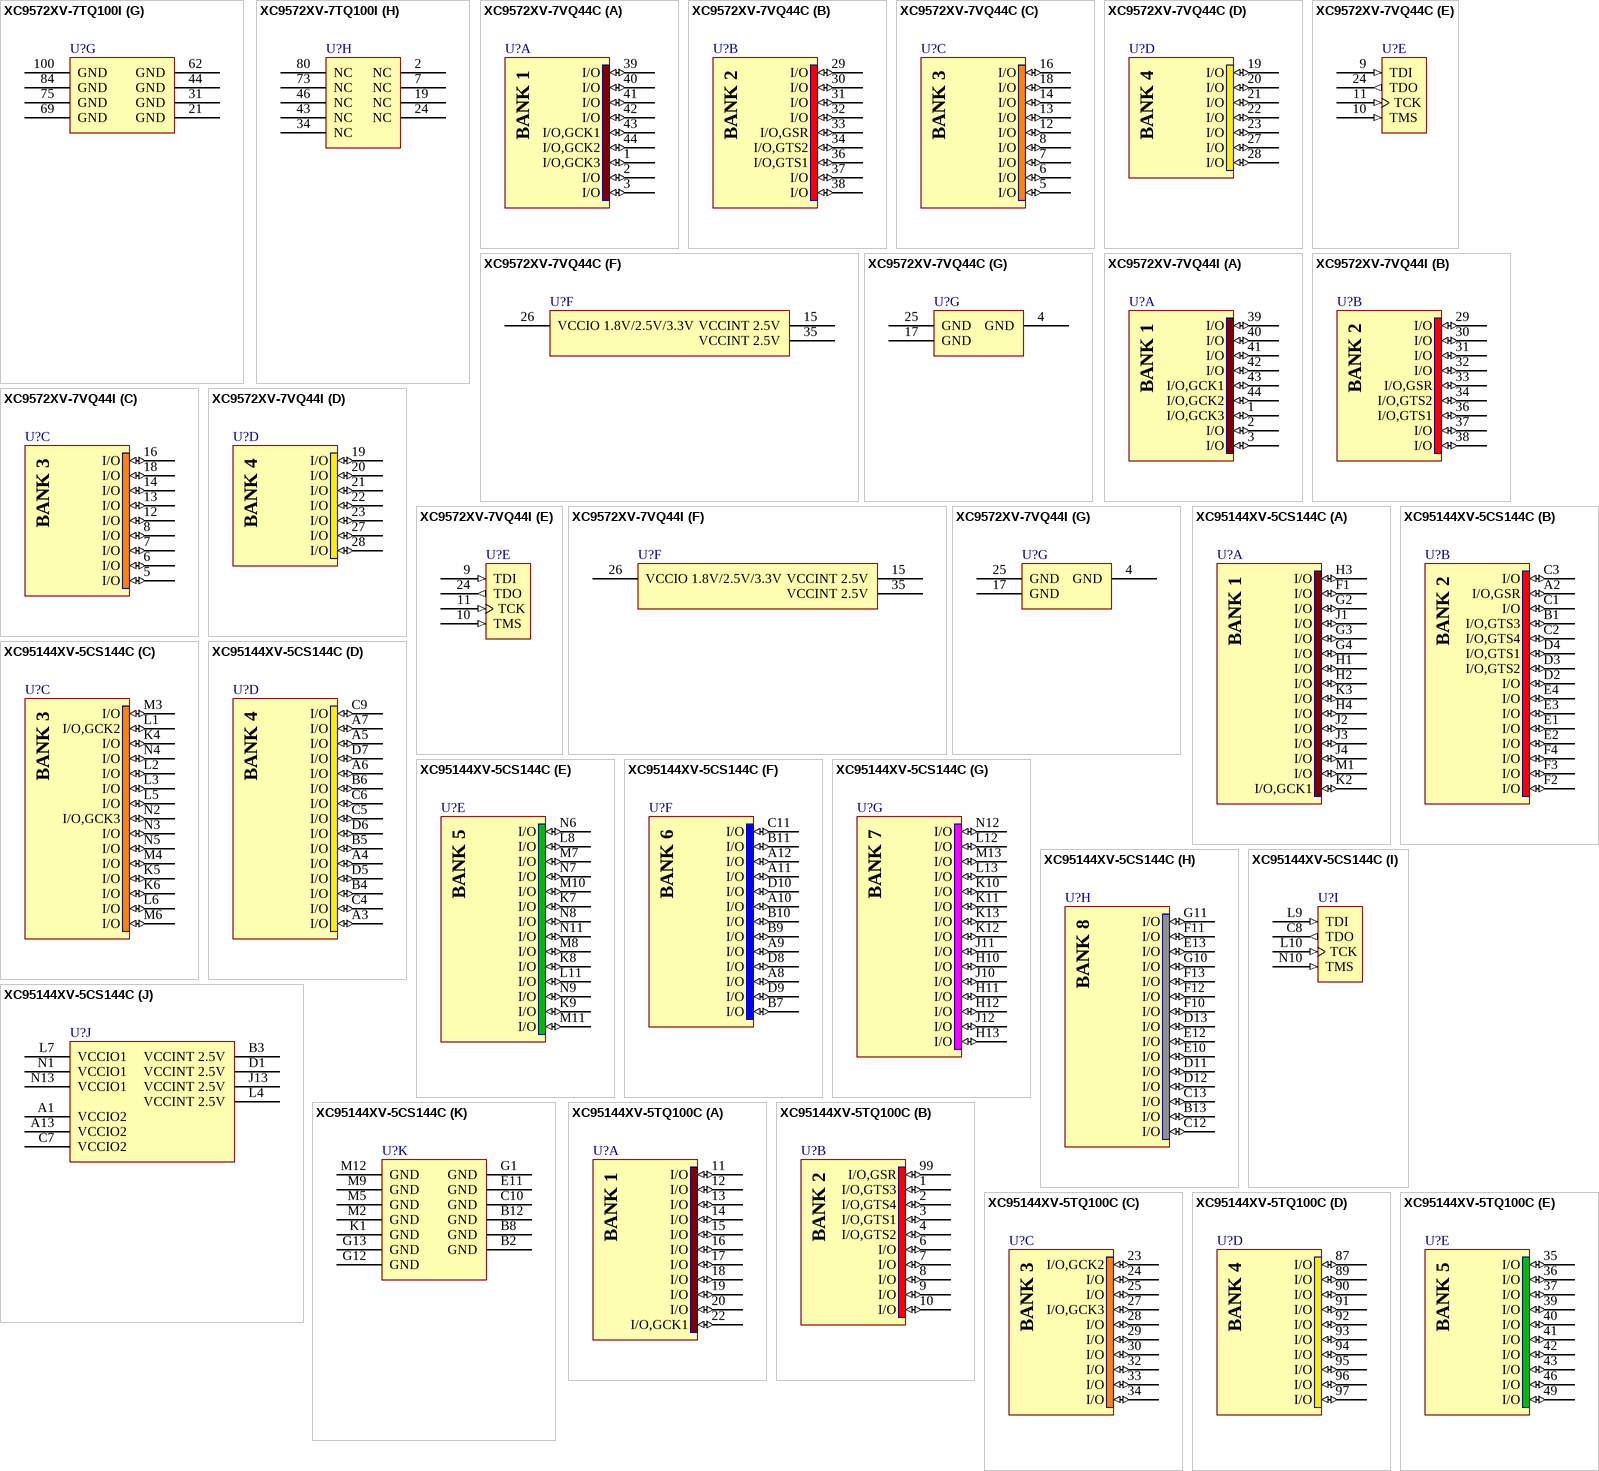
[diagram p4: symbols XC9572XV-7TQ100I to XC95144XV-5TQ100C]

## XC9572XV-7TQ100I
designator U?
XC9500XV, 2.5V High-Performance 72 Macrocell CPLD, 72 User I/Os, 100-Pin TQFP, Speed Grade 7, Industrial Grade
footprint TQ100_N (Thin QFP, 100-Leads, Body 14x14mm, Pitch 0.5mm, IPC Medium Density)
footprint TQ100_L (Thin QFP, 100-Leads, Body 14x14mm, Pitch 0.5mm, IPC High Density)
footprint TQ100_M (Thin QFP, 100-Leads, Body 14x14mm, Pitch 0.5mm, IPC Low Density)
signal-integrity model XC9572XV_TQ100 (XC9500XV)
part A pins: 13 I/O (io), 14 I/O (io), 15 I/O (io), 16 I/O (io), 17 I/O (io), 18 I/O (io), 20 I/O (io), 22 I/O,GCK1 (io), 23 I/O,GCK2 (io), 25 I/O (io), 27 I/O,GCK3 (io), 28 I/O (io), 29 I/O (io), 30 I/O (io), 33 I/O (io), 36 I/O (io), 39 I/O (io), 40 I/O (io)
part B pins: 1 I/O (io), 3 I/O,GTS1 (io), 4 I/O,GTS2 (io), 6 I/O (io), 8 I/O (io), 9 I/O (io), 10 I/O (io), 11 I/O (io), 12 I/O (io), 87 I/O (io), 91 I/O (io), 92 I/O (io), 93 I/O (io), 94 I/O (io), 95 I/O (io), 96 I/O (io), 97 I/O (io), 99 I/O,GSR (io)
part C pins: 32 I/O (io), 35 I/O (io), 37 I/O (io), 41 I/O (io), 42 I/O (io), 49 I/O (io), 50 I/O (io), 52 I/O (io), 53 I/O (io), 54 I/O (io), 55 I/O (io), 56 I/O (io), 58 I/O (io), 59 I/O (io), 60 I/O (io), 61 I/O (io), 63 I/O (io), 64 I/O (io)
part D pins: 65 I/O (io), 66 I/O (io), 67 I/O (io), 68 I/O (io), 70 I/O (io), 71 I/O (io), 72 I/O (io), 74 I/O (io), 76 I/O (io), 77 I/O (io), 78 I/O (io), 79 I/O (io), 81 I/O (io), 82 I/O (io), 85 I/O (io), 86 I/O (io), 89 I/O (io), 90 I/O (io)
part E pins: 45 TDI (in), 47 TMS (in), 48 TCK (in), 83 TDO (out)
part F pins: 5 VCCINT 2.5V (power), 26 VCCIO 1.8V/2.5V/3.3V (power), 38 VCCIO 1.8V/2.5V/3.3V (power), 51 VCCIO 1.8V/2.5V/3.3V (power), 57 VCCINT 2.5V (power), 88 VCCIO 1.8V/2.5V/3.3V (power), 98 VCCINT 2.5V (power)
part G pins: 21 GND (power), 31 GND (power), 44 GND (power), 62 GND (power), 69 GND (power), 75 GND (power), 84 GND (power), 100 GND (power)
part H pins: 2 NC, 7 NC, 19 NC, 24 NC, 34 NC, 43 NC, 46 NC, 73 NC, 80 NC

## XC9572XV-7VQ44C
designator U?
XC9500XV, 2.5V High-Performance 72 Macrocell CPLD, 34 User I/Os, 44-Pin VQFP, Speed Grade 7, Commercial Grade
footprint VQ44_N (Thin QFP, 44-Leads, Body 10x10mm, Pitch 0.8mm, IPC Medium Density)
footprint VQ44_L (Thin QFP, 44-Leads, Body 10x10mm, Pitch 0.8mm, IPC High Density)
footprint VQ44_M (Thin QFP, 44-Leads, Body 10x10mm, Pitch 0.8mm, IPC Low Density)
signal-integrity model XC9572XV_VQ44 (XC9500XV)
part A pins: 1 I/O,GCK3 (io), 2 I/O (io), 3 I/O (io), 39 I/O (io), 40 I/O (io), 41 I/O (io), 42 I/O (io), 43 I/O,GCK1 (io), 44 I/O,GCK2 (io)
part B pins: 29 I/O (io), 30 I/O (io), 31 I/O (io), 32 I/O (io), 33 I/O,GSR (io), 34 I/O,GTS2 (io), 36 I/O,GTS1 (io), 37 I/O (io), 38 I/O (io)
part C pins: 5 I/O (io), 6 I/O (io), 7 I/O (io), 8 I/O (io), 12 I/O (io), 13 I/O (io), 14 I/O (io), 16 I/O (io), 18 I/O (io)
part D pins: 19 I/O (io), 20 I/O (io), 21 I/O (io), 22 I/O (io), 23 I/O (io), 27 I/O (io), 28 I/O (io)
part E pins: 9 TDI (in), 10 TMS (in), 11 TCK (in), 24 TDO (out)
part F pins: 15 VCCINT 2.5V (power), 26 VCCIO 1.8V/2.5V/3.3V (power), 35 VCCINT 2.5V (power)
part G pins: 4 GND (power), 17 GND (power), 25 GND (power)

## XC9572XV-7VQ44I
designator U?
XC9500XV, 2.5V High-Performance 72 Macrocell CPLD, 34 User I/Os, 44-Pin VQFP, Speed Grade 7, Industrial Grade
footprint VQ44_N (Thin QFP, 44-Leads, Body 10x10mm, Pitch 0.8mm, IPC Medium Density)
footprint VQ44_L (Thin QFP, 44-Leads, Body 10x10mm, Pitch 0.8mm, IPC High Density)
footprint VQ44_M (Thin QFP, 44-Leads, Body 10x10mm, Pitch 0.8mm, IPC Low Density)
signal-integrity model XC9572XV_VQ44 (XC9500XV)
part A pins: 1 I/O,GCK3 (io), 2 I/O (io), 3 I/O (io), 39 I/O (io), 40 I/O (io), 41 I/O (io), 42 I/O (io), 43 I/O,GCK1 (io), 44 I/O,GCK2 (io)
part B pins: 29 I/O (io), 30 I/O (io), 31 I/O (io), 32 I/O (io), 33 I/O,GSR (io), 34 I/O,GTS2 (io), 36 I/O,GTS1 (io), 37 I/O (io), 38 I/O (io)
part C pins: 5 I/O (io), 6 I/O (io), 7 I/O (io), 8 I/O (io), 12 I/O (io), 13 I/O (io), 14 I/O (io), 16 I/O (io), 18 I/O (io)
part D pins: 19 I/O (io), 20 I/O (io), 21 I/O (io), 22 I/O (io), 23 I/O (io), 27 I/O (io), 28 I/O (io)
part E pins: 9 TDI (in), 10 TMS (in), 11 TCK (in), 24 TDO (out)
part F pins: 15 VCCINT 2.5V (power), 26 VCCIO 1.8V/2.5V/3.3V (power), 35 VCCINT 2.5V (power)
part G pins: 4 GND (power), 17 GND (power), 25 GND (power)

## XC95144XV-5CS144C
designator U?
XC9500XV, 2.5V High-Performance 144 Macrocell CPLD, 117 User I/Os, 144-Ball CSBGA, Speed Grade 5, Commercial Grade
footprint CS144 (BGA, 144-Leads, Body 12x12mm, Pitch 0.8mm)
signal-integrity model XC95144XV_CS144 (XC9500XV)
part A pins: F1 I/O (io), G2 I/O (io), G3 I/O (io), G4 I/O (io), H1 I/O (io), H2 I/O (io), H3 I/O (io), H4 I/O (io), J1 I/O (io), J2 I/O (io), J3 I/O (io), J4 I/O (io), K2 I/O,GCK1 (io), K3 I/O (io), M1 I/O (io)
part B pins: A2 I/O,GSR (io), B1 I/O,GTS3 (io), C1 I/O (io), C2 I/O,GTS4 (io), C3 I/O (io), D2 I/O (io), D3 I/O,GTS2 (io), D4 I/O,GTS1 (io), E1 I/O (io), E2 I/O (io), E3 I/O (io), E4 I/O (io), F2 I/O (io), F3 I/O (io), F4 I/O (io)
part C pins: K4 I/O (io), K5 I/O (io), K6 I/O (io), L1 I/O,GCK2 (io), L2 I/O (io), L3 I/O (io), L5 I/O (io), L6 I/O (io), M3 I/O (io), M4 I/O (io), M6 I/O (io), N2 I/O,GCK3 (io), N3 I/O (io), N4 I/O (io), N5 I/O (io)
part D pins: A3 I/O (io), A4 I/O (io), A5 I/O (io), A6 I/O (io), A7 I/O (io), B4 I/O (io), B5 I/O (io), B6 I/O (io), C4 I/O (io), C5 I/O (io), C6 I/O (io), C9 I/O (io), D5 I/O (io), D6 I/O (io), D7 I/O (io)
part E pins: K7 I/O (io), K8 I/O (io), K9 I/O (io), L8 I/O (io), L11 I/O (io), M7 I/O (io), M8 I/O (io), M10 I/O (io), M11 I/O (io), N6 I/O (io), N7 I/O (io), N8 I/O (io), N9 I/O (io), N11 I/O (io)
part F pins: A8 I/O (io), A9 I/O (io), A10 I/O (io), A11 I/O (io), A12 I/O (io), B7 I/O (io), B9 I/O (io), B10 I/O (io), B11 I/O (io), C11 I/O (io), D8 I/O (io), D9 I/O (io), D10 I/O (io)
part G pins: H10 I/O (io), H11 I/O (io), H12 I/O (io), H13 I/O (io), J10 I/O (io), J11 I/O (io), J12 I/O (io), K10 I/O (io), K11 I/O (io), K12 I/O (io), K13 I/O (io), L12 I/O (io), L13 I/O (io), M13 I/O (io), N12 I/O (io)
part H pins: B13 I/O (io), C12 I/O (io), C13 I/O (io), D11 I/O (io), D12 I/O (io), D13 I/O (io), E10 I/O (io), E12 I/O (io), E13 I/O (io), F10 I/O (io), F11 I/O (io), F12 I/O (io), F13 I/O (io), G10 I/O (io), G11 I/O (io)
part I pins: C8 TDO (out), L9 TDI (in), L10 TCK (in), N10 TMS (in)
part J pins: A1 VCCIO2 (power), A13 VCCIO2 (power), B3 VCCINT 2.5V (power), C7 VCCIO2 (power), D1 VCCINT 2.5V (power), J13 VCCINT 2.5V (power), L4 VCCINT 2.5V (power), L7 VCCIO1 (power), N1 VCCIO1 (power), N13 VCCIO1 (power)
part K pins: B2 GND (power), B8 GND (power), B12 GND (power), C10 GND (power), E11 GND (power), G1 GND (power), G12 GND (power), G13 GND (power), K1 GND (power), M2 GND (power), M5 GND (power), M9 GND (power), M12 GND (power)

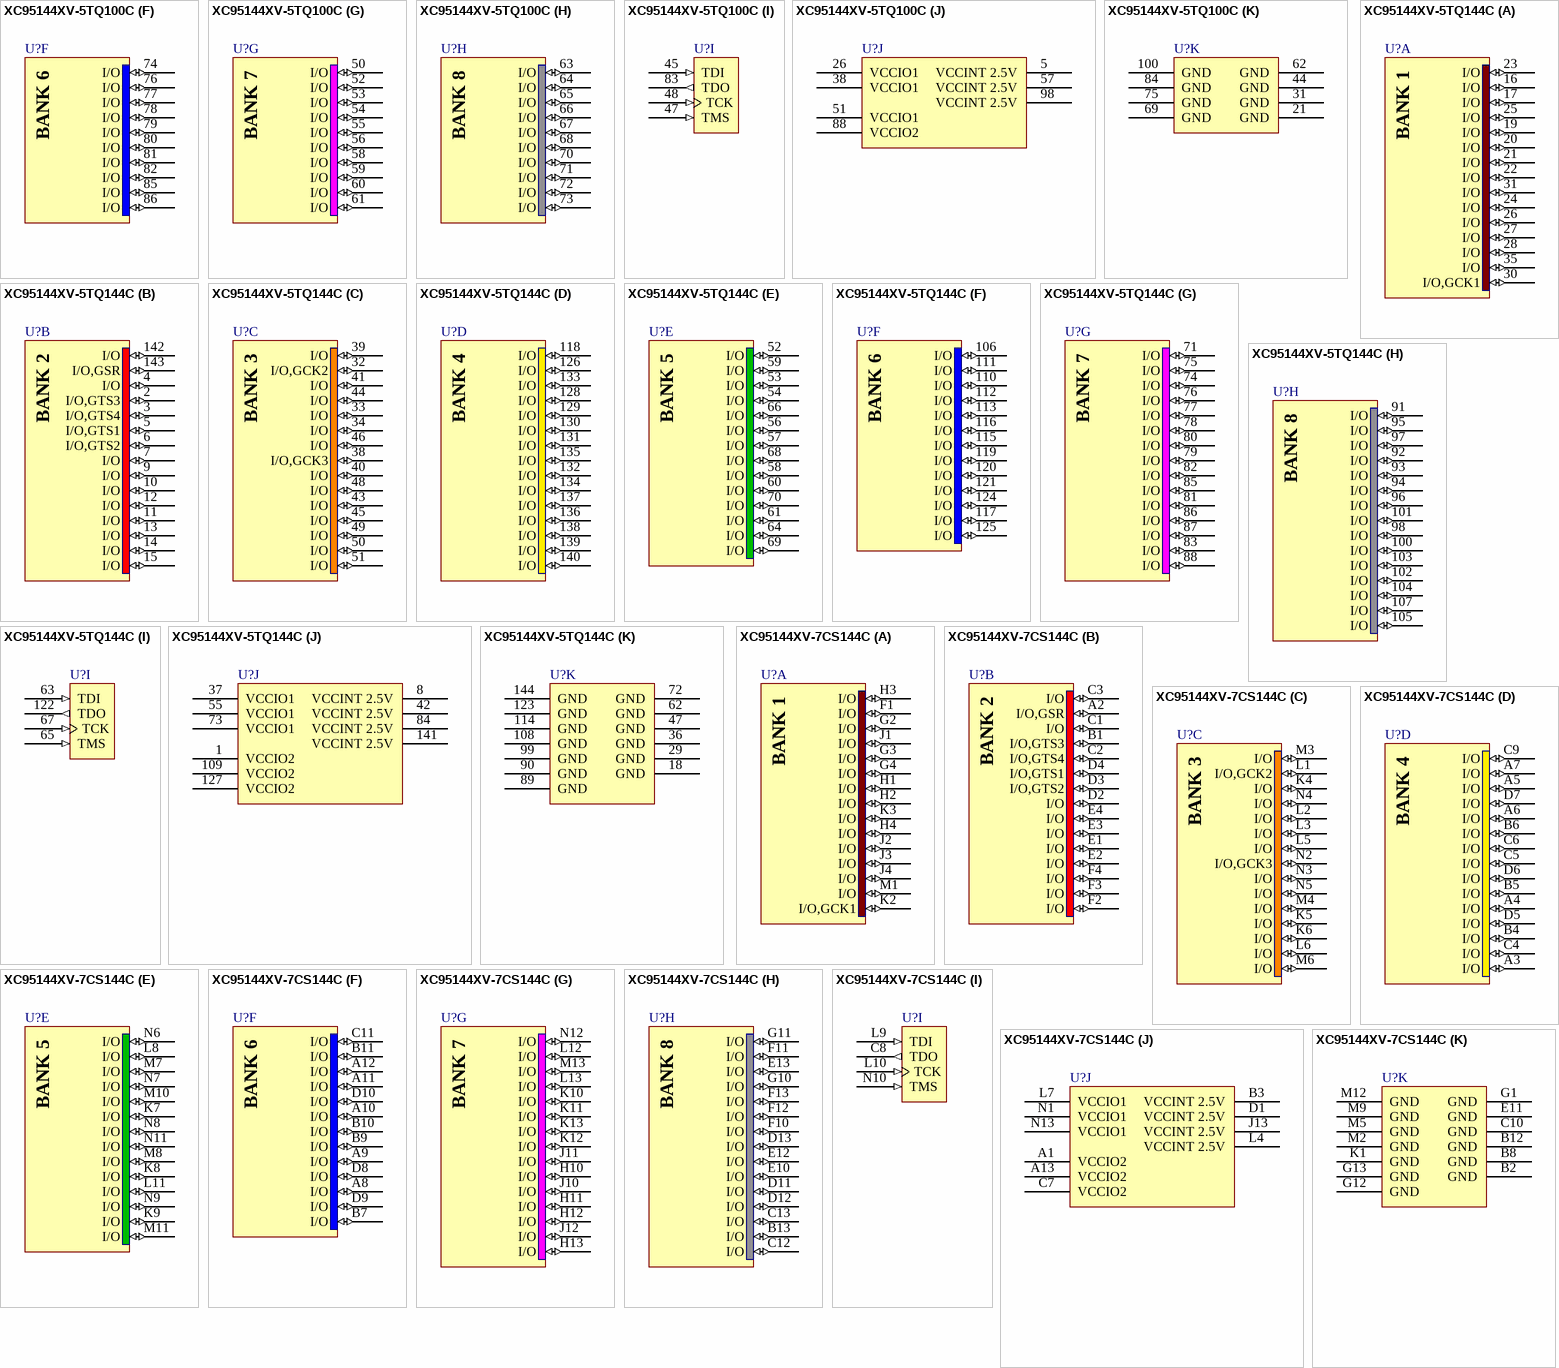
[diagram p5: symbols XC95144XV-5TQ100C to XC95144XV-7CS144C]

## XC95144XV-5TQ100C
designator U?
XC9500XV, 2.5V High-Performance 144 Macrocell CPLD, 81 User I/Os, 100-Pin TQFP, Speed Grade 5, Commercial Grade
footprint TQ100_N (Thin QFP, 100-Leads, Body 14x14mm, Pitch 0.5mm, IPC Medium Density)
footprint TQ100_L (Thin QFP, 100-Leads, Body 14x14mm, Pitch 0.5mm, IPC High Density)
footprint TQ100_M (Thin QFP, 100-Leads, Body 14x14mm, Pitch 0.5mm, IPC Low Density)
signal-integrity model XC95144XV_TQ100 (XC9500XV)
part A pins: 11 I/O (io), 12 I/O (io), 13 I/O (io), 14 I/O (io), 15 I/O (io), 16 I/O (io), 17 I/O (io), 18 I/O (io), 19 I/O (io), 20 I/O (io), 22 I/O,GCK1 (io)
part B pins: 1 I/O,GTS3 (io), 2 I/O,GTS4 (io), 3 I/O,GTS1 (io), 4 I/O,GTS2 (io), 6 I/O (io), 7 I/O (io), 8 I/O (io), 9 I/O (io), 10 I/O (io), 99 I/O,GSR (io)
part C pins: 23 I/O,GCK2 (io), 24 I/O (io), 25 I/O (io), 27 I/O,GCK3 (io), 28 I/O (io), 29 I/O (io), 30 I/O (io), 32 I/O (io), 33 I/O (io), 34 I/O (io)
part D pins: 87 I/O (io), 89 I/O (io), 90 I/O (io), 91 I/O (io), 92 I/O (io), 93 I/O (io), 94 I/O (io), 95 I/O (io), 96 I/O (io), 97 I/O (io)
part E pins: 35 I/O (io), 36 I/O (io), 37 I/O (io), 39 I/O (io), 40 I/O (io), 41 I/O (io), 42 I/O (io), 43 I/O (io), 46 I/O (io), 49 I/O (io)
part F pins: 74 I/O (io), 76 I/O (io), 77 I/O (io), 78 I/O (io), 79 I/O (io), 80 I/O (io), 81 I/O (io), 82 I/O (io), 85 I/O (io), 86 I/O (io)
part G pins: 50 I/O (io), 52 I/O (io), 53 I/O (io), 54 I/O (io), 55 I/O (io), 56 I/O (io), 58 I/O (io), 59 I/O (io), 60 I/O (io), 61 I/O (io)
part H pins: 63 I/O (io), 64 I/O (io), 65 I/O (io), 66 I/O (io), 67 I/O (io), 68 I/O (io), 70 I/O (io), 71 I/O (io), 72 I/O (io), 73 I/O (io)
part I pins: 45 TDI (in), 47 TMS (in), 48 TCK (in), 83 TDO (out)
part J pins: 5 VCCINT 2.5V (power), 26 VCCIO1 (power), 38 VCCIO1 (power), 51 VCCIO1 (power), 57 VCCINT 2.5V (power), 88 VCCIO2 (power), 98 VCCINT 2.5V (power)
part K pins: 21 GND (power), 31 GND (power), 44 GND (power), 62 GND (power), 69 GND (power), 75 GND (power), 84 GND (power), 100 GND (power)

## XC95144XV-5TQ144C
designator U?
XC9500XV, 2.5V High-Performance 144 Macrocell CPLD, 117 User I/Os, 144-Pin TQFP, Speed Grade 5, Commercial Grade
footprint TQ144_N (Thin QFP, 144-Leads, Body 20x20mm, Pitch 0.5mm, IPC Medium Density)
footprint TQ144_L (Thin QFP, 144-Leads, Body 20x20mm, Pitch 0.5mm, IPC High Density)
footprint TQ144_M (Thin QFP, 144-Leads, Body 20x20mm, Pitch 0.5mm, IPC Low Density)
signal-integrity model XC95144XV_TQ144 (XC9500XV)
part A pins: 16 I/O (io), 17 I/O (io), 19 I/O (io), 20 I/O (io), 21 I/O (io), 22 I/O (io), 23 I/O (io), 24 I/O (io), 25 I/O (io), 26 I/O (io), 27 I/O (io), 28 I/O (io), 30 I/O,GCK1 (io), 31 I/O (io), 35 I/O (io)
part B pins: 2 I/O,GTS3 (io), 3 I/O,GTS4 (io), 4 I/O (io), 5 I/O,GTS1 (io), 6 I/O,GTS2 (io), 7 I/O (io), 9 I/O (io), 10 I/O (io), 11 I/O (io), 12 I/O (io), 13 I/O (io), 14 I/O (io), 15 I/O (io), 142 I/O (io), 143 I/O,GSR (io)
part C pins: 32 I/O,GCK2 (io), 33 I/O (io), 34 I/O (io), 38 I/O,GCK3 (io), 39 I/O (io), 40 I/O (io), 41 I/O (io), 43 I/O (io), 44 I/O (io), 45 I/O (io), 46 I/O (io), 48 I/O (io), 49 I/O (io), 50 I/O (io), 51 I/O (io)
part D pins: 118 I/O (io), 126 I/O (io), 128 I/O (io), 129 I/O (io), 130 I/O (io), 131 I/O (io), 132 I/O (io), 133 I/O (io), 134 I/O (io), 135 I/O (io), 136 I/O (io), 137 I/O (io), 138 I/O (io), 139 I/O (io), 140 I/O (io)
part E pins: 52 I/O (io), 53 I/O (io), 54 I/O (io), 56 I/O (io), 57 I/O (io), 58 I/O (io), 59 I/O (io), 60 I/O (io), 61 I/O (io), 64 I/O (io), 66 I/O (io), 68 I/O (io), 69 I/O (io), 70 I/O (io)
part F pins: 106 I/O (io), 110 I/O (io), 111 I/O (io), 112 I/O (io), 113 I/O (io), 115 I/O (io), 116 I/O (io), 117 I/O (io), 119 I/O (io), 120 I/O (io), 121 I/O (io), 124 I/O (io), 125 I/O (io)
part G pins: 71 I/O (io), 74 I/O (io), 75 I/O (io), 76 I/O (io), 77 I/O (io), 78 I/O (io), 79 I/O (io), 80 I/O (io), 81 I/O (io), 82 I/O (io), 83 I/O (io), 85 I/O (io), 86 I/O (io), 87 I/O (io), 88 I/O (io)
part H pins: 91 I/O (io), 92 I/O (io), 93 I/O (io), 94 I/O (io), 95 I/O (io), 96 I/O (io), 97 I/O (io), 98 I/O (io), 100 I/O (io), 101 I/O (io), 102 I/O (io), 103 I/O (io), 104 I/O (io), 105 I/O (io), 107 I/O (io)
part I pins: 63 TDI (in), 65 TMS (in), 67 TCK (in), 122 TDO (out)
part J pins: 1 VCCIO2 (power), 8 VCCINT 2.5V (power), 37 VCCIO1 (power), 42 VCCINT 2.5V (power), 55 VCCIO1 (power), 73 VCCIO1 (power), 84 VCCINT 2.5V (power), 109 VCCIO2 (power), 127 VCCIO2 (power), 141 VCCINT 2.5V (power)
part K pins: 18 GND (power), 29 GND (power), 36 GND (power), 47 GND (power), 62 GND (power), 72 GND (power), 89 GND (power), 90 GND (power), 99 GND (power), 108 GND (power), 114 GND (power), 123 GND (power), 144 GND (power)

## XC95144XV-7CS144C
designator U?
XC9500XV, 2.5V High-Performance 144 Macrocell CPLD, 117 User I/Os, 144-Ball CSBGA, Speed Grade 7, Commercial Grade
footprint CS144 (BGA, 144-Leads, Body 12x12mm, Pitch 0.8mm)
signal-integrity model XC95144XV_CS144 (XC9500XV)
part A pins: F1 I/O (io), G2 I/O (io), G3 I/O (io), G4 I/O (io), H1 I/O (io), H2 I/O (io), H3 I/O (io), H4 I/O (io), J1 I/O (io), J2 I/O (io), J3 I/O (io), J4 I/O (io), K2 I/O,GCK1 (io), K3 I/O (io), M1 I/O (io)
part B pins: A2 I/O,GSR (io), B1 I/O,GTS3 (io), C1 I/O (io), C2 I/O,GTS4 (io), C3 I/O (io), D2 I/O (io), D3 I/O,GTS2 (io), D4 I/O,GTS1 (io), E1 I/O (io), E2 I/O (io), E3 I/O (io), E4 I/O (io), F2 I/O (io), F3 I/O (io), F4 I/O (io)
part C pins: K4 I/O (io), K5 I/O (io), K6 I/O (io), L1 I/O,GCK2 (io), L2 I/O (io), L3 I/O (io), L5 I/O (io), L6 I/O (io), M3 I/O (io), M4 I/O (io), M6 I/O (io), N2 I/O,GCK3 (io), N3 I/O (io), N4 I/O (io), N5 I/O (io)
part D pins: A3 I/O (io), A4 I/O (io), A5 I/O (io), A6 I/O (io), A7 I/O (io), B4 I/O (io), B5 I/O (io), B6 I/O (io), C4 I/O (io), C5 I/O (io), C6 I/O (io), C9 I/O (io), D5 I/O (io), D6 I/O (io), D7 I/O (io)
part E pins: K7 I/O (io), K8 I/O (io), K9 I/O (io), L8 I/O (io), L11 I/O (io), M7 I/O (io), M8 I/O (io), M10 I/O (io), M11 I/O (io), N6 I/O (io), N7 I/O (io), N8 I/O (io), N9 I/O (io), N11 I/O (io)
part F pins: A8 I/O (io), A9 I/O (io), A10 I/O (io), A11 I/O (io), A12 I/O (io), B7 I/O (io), B9 I/O (io), B10 I/O (io), B11 I/O (io), C11 I/O (io), D8 I/O (io), D9 I/O (io), D10 I/O (io)
part G pins: H10 I/O (io), H11 I/O (io), H12 I/O (io), H13 I/O (io), J10 I/O (io), J11 I/O (io), J12 I/O (io), K10 I/O (io), K11 I/O (io), K12 I/O (io), K13 I/O (io), L12 I/O (io), L13 I/O (io), M13 I/O (io), N12 I/O (io)
part H pins: B13 I/O (io), C12 I/O (io), C13 I/O (io), D11 I/O (io), D12 I/O (io), D13 I/O (io), E10 I/O (io), E12 I/O (io), E13 I/O (io), F10 I/O (io), F11 I/O (io), F12 I/O (io), F13 I/O (io), G10 I/O (io), G11 I/O (io)
part I pins: C8 TDO (out), L9 TDI (in), L10 TCK (in), N10 TMS (in)
part J pins: A1 VCCIO2 (power), A13 VCCIO2 (power), B3 VCCINT 2.5V (power), C7 VCCIO2 (power), D1 VCCINT 2.5V (power), J13 VCCINT 2.5V (power), L4 VCCINT 2.5V (power), L7 VCCIO1 (power), N1 VCCIO1 (power), N13 VCCIO1 (power)
part K pins: B2 GND (power), B8 GND (power), B12 GND (power), C10 GND (power), E11 GND (power), G1 GND (power), G12 GND (power), G13 GND (power), K1 GND (power), M2 GND (power), M5 GND (power), M9 GND (power), M12 GND (power)

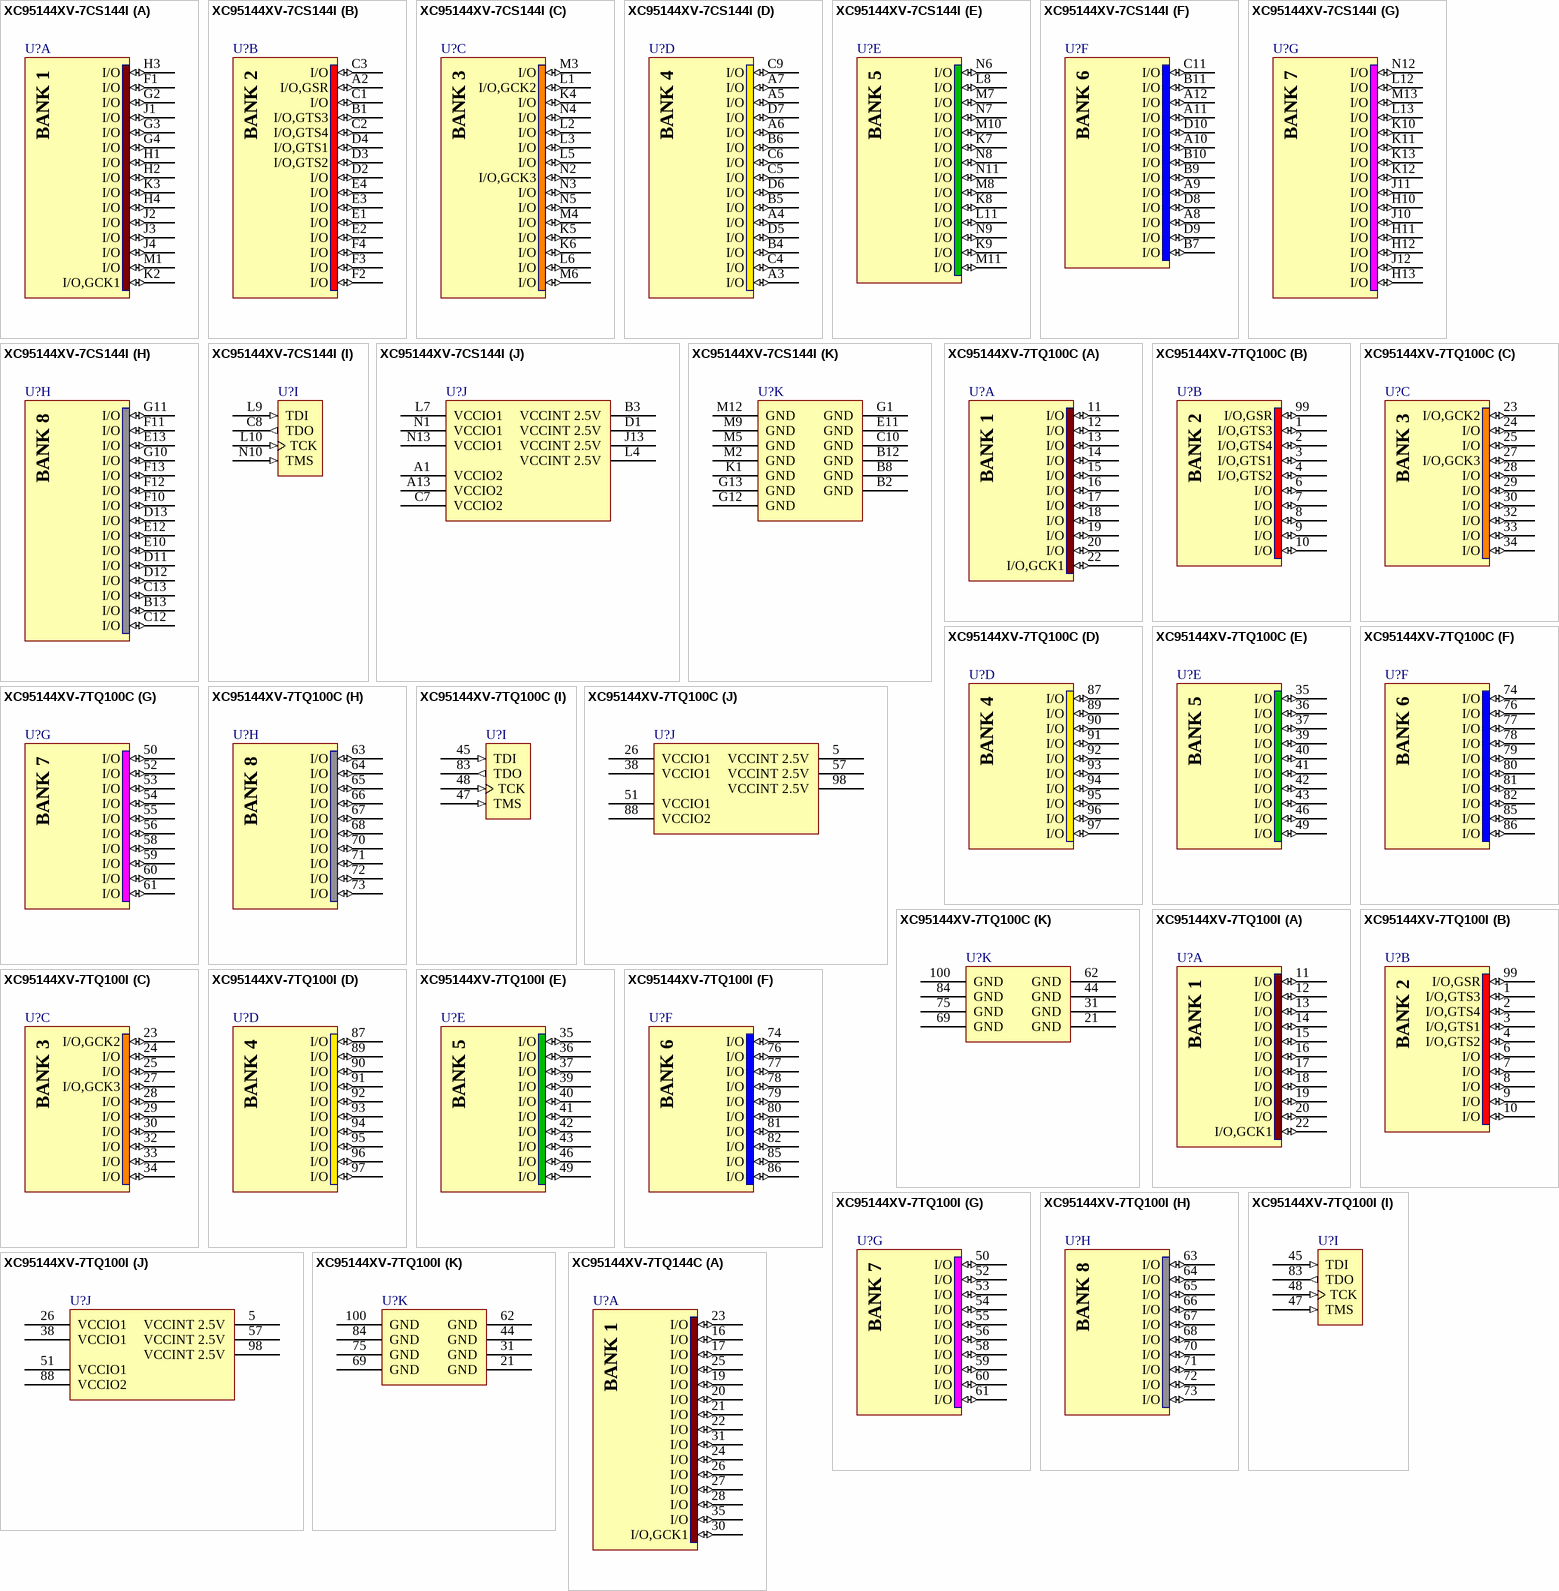
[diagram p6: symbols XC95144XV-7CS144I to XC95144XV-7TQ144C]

## XC95144XV-7CS144I
designator U?
XC9500XV, 2.5V High-Performance 144 Macrocell CPLD, 117 User I/Os, 144-Ball CSBGA, Speed Grade 7, Industrial Grade
footprint CS144 (BGA, 144-Leads, Body 12x12mm, Pitch 0.8mm)
signal-integrity model XC95144XV_CS144 (XC9500XV)
part A pins: F1 I/O (io), G2 I/O (io), G3 I/O (io), G4 I/O (io), H1 I/O (io), H2 I/O (io), H3 I/O (io), H4 I/O (io), J1 I/O (io), J2 I/O (io), J3 I/O (io), J4 I/O (io), K2 I/O,GCK1 (io), K3 I/O (io), M1 I/O (io)
part B pins: A2 I/O,GSR (io), B1 I/O,GTS3 (io), C1 I/O (io), C2 I/O,GTS4 (io), C3 I/O (io), D2 I/O (io), D3 I/O,GTS2 (io), D4 I/O,GTS1 (io), E1 I/O (io), E2 I/O (io), E3 I/O (io), E4 I/O (io), F2 I/O (io), F3 I/O (io), F4 I/O (io)
part C pins: K4 I/O (io), K5 I/O (io), K6 I/O (io), L1 I/O,GCK2 (io), L2 I/O (io), L3 I/O (io), L5 I/O (io), L6 I/O (io), M3 I/O (io), M4 I/O (io), M6 I/O (io), N2 I/O,GCK3 (io), N3 I/O (io), N4 I/O (io), N5 I/O (io)
part D pins: A3 I/O (io), A4 I/O (io), A5 I/O (io), A6 I/O (io), A7 I/O (io), B4 I/O (io), B5 I/O (io), B6 I/O (io), C4 I/O (io), C5 I/O (io), C6 I/O (io), C9 I/O (io), D5 I/O (io), D6 I/O (io), D7 I/O (io)
part E pins: K7 I/O (io), K8 I/O (io), K9 I/O (io), L8 I/O (io), L11 I/O (io), M7 I/O (io), M8 I/O (io), M10 I/O (io), M11 I/O (io), N6 I/O (io), N7 I/O (io), N8 I/O (io), N9 I/O (io), N11 I/O (io)
part F pins: A8 I/O (io), A9 I/O (io), A10 I/O (io), A11 I/O (io), A12 I/O (io), B7 I/O (io), B9 I/O (io), B10 I/O (io), B11 I/O (io), C11 I/O (io), D8 I/O (io), D9 I/O (io), D10 I/O (io)
part G pins: H10 I/O (io), H11 I/O (io), H12 I/O (io), H13 I/O (io), J10 I/O (io), J11 I/O (io), J12 I/O (io), K10 I/O (io), K11 I/O (io), K12 I/O (io), K13 I/O (io), L12 I/O (io), L13 I/O (io), M13 I/O (io), N12 I/O (io)
part H pins: B13 I/O (io), C12 I/O (io), C13 I/O (io), D11 I/O (io), D12 I/O (io), D13 I/O (io), E10 I/O (io), E12 I/O (io), E13 I/O (io), F10 I/O (io), F11 I/O (io), F12 I/O (io), F13 I/O (io), G10 I/O (io), G11 I/O (io)
part I pins: C8 TDO (out), L9 TDI (in), L10 TCK (in), N10 TMS (in)
part J pins: A1 VCCIO2 (power), A13 VCCIO2 (power), B3 VCCINT 2.5V (power), C7 VCCIO2 (power), D1 VCCINT 2.5V (power), J13 VCCINT 2.5V (power), L4 VCCINT 2.5V (power), L7 VCCIO1 (power), N1 VCCIO1 (power), N13 VCCIO1 (power)
part K pins: B2 GND (power), B8 GND (power), B12 GND (power), C10 GND (power), E11 GND (power), G1 GND (power), G12 GND (power), G13 GND (power), K1 GND (power), M2 GND (power), M5 GND (power), M9 GND (power), M12 GND (power)

## XC95144XV-7TQ100C
designator U?
XC9500XV, 2.5V High-Performance 144 Macrocell CPLD, 81 User I/Os, 100-Pin TQFP, Speed Grade 7, Commercial Grade
footprint TQ100_N (Thin QFP, 100-Leads, Body 14x14mm, Pitch 0.5mm, IPC Medium Density)
footprint TQ100_L (Thin QFP, 100-Leads, Body 14x14mm, Pitch 0.5mm, IPC High Density)
footprint TQ100_M (Thin QFP, 100-Leads, Body 14x14mm, Pitch 0.5mm, IPC Low Density)
signal-integrity model XC95144XV_TQ100 (XC9500XV)
part A pins: 11 I/O (io), 12 I/O (io), 13 I/O (io), 14 I/O (io), 15 I/O (io), 16 I/O (io), 17 I/O (io), 18 I/O (io), 19 I/O (io), 20 I/O (io), 22 I/O,GCK1 (io)
part B pins: 1 I/O,GTS3 (io), 2 I/O,GTS4 (io), 3 I/O,GTS1 (io), 4 I/O,GTS2 (io), 6 I/O (io), 7 I/O (io), 8 I/O (io), 9 I/O (io), 10 I/O (io), 99 I/O,GSR (io)
part C pins: 23 I/O,GCK2 (io), 24 I/O (io), 25 I/O (io), 27 I/O,GCK3 (io), 28 I/O (io), 29 I/O (io), 30 I/O (io), 32 I/O (io), 33 I/O (io), 34 I/O (io)
part D pins: 87 I/O (io), 89 I/O (io), 90 I/O (io), 91 I/O (io), 92 I/O (io), 93 I/O (io), 94 I/O (io), 95 I/O (io), 96 I/O (io), 97 I/O (io)
part E pins: 35 I/O (io), 36 I/O (io), 37 I/O (io), 39 I/O (io), 40 I/O (io), 41 I/O (io), 42 I/O (io), 43 I/O (io), 46 I/O (io), 49 I/O (io)
part F pins: 74 I/O (io), 76 I/O (io), 77 I/O (io), 78 I/O (io), 79 I/O (io), 80 I/O (io), 81 I/O (io), 82 I/O (io), 85 I/O (io), 86 I/O (io)
part G pins: 50 I/O (io), 52 I/O (io), 53 I/O (io), 54 I/O (io), 55 I/O (io), 56 I/O (io), 58 I/O (io), 59 I/O (io), 60 I/O (io), 61 I/O (io)
part H pins: 63 I/O (io), 64 I/O (io), 65 I/O (io), 66 I/O (io), 67 I/O (io), 68 I/O (io), 70 I/O (io), 71 I/O (io), 72 I/O (io), 73 I/O (io)
part I pins: 45 TDI (in), 47 TMS (in), 48 TCK (in), 83 TDO (out)
part J pins: 5 VCCINT 2.5V (power), 26 VCCIO1 (power), 38 VCCIO1 (power), 51 VCCIO1 (power), 57 VCCINT 2.5V (power), 88 VCCIO2 (power), 98 VCCINT 2.5V (power)
part K pins: 21 GND (power), 31 GND (power), 44 GND (power), 62 GND (power), 69 GND (power), 75 GND (power), 84 GND (power), 100 GND (power)

## XC95144XV-7TQ100I
designator U?
XC9500XV, 2.5V High-Performance 144 Macrocell CPLD, 81 User I/Os, 100-Pin TQFP, Speed Grade 7, Industrial Grade
footprint TQ100_N (Thin QFP, 100-Leads, Body 14x14mm, Pitch 0.5mm, IPC Medium Density)
footprint TQ100_L (Thin QFP, 100-Leads, Body 14x14mm, Pitch 0.5mm, IPC High Density)
footprint TQ100_M (Thin QFP, 100-Leads, Body 14x14mm, Pitch 0.5mm, IPC Low Density)
signal-integrity model XC95144XV_TQ100 (XC9500XV)
part A pins: 11 I/O (io), 12 I/O (io), 13 I/O (io), 14 I/O (io), 15 I/O (io), 16 I/O (io), 17 I/O (io), 18 I/O (io), 19 I/O (io), 20 I/O (io), 22 I/O,GCK1 (io)
part B pins: 1 I/O,GTS3 (io), 2 I/O,GTS4 (io), 3 I/O,GTS1 (io), 4 I/O,GTS2 (io), 6 I/O (io), 7 I/O (io), 8 I/O (io), 9 I/O (io), 10 I/O (io), 99 I/O,GSR (io)
part C pins: 23 I/O,GCK2 (io), 24 I/O (io), 25 I/O (io), 27 I/O,GCK3 (io), 28 I/O (io), 29 I/O (io), 30 I/O (io), 32 I/O (io), 33 I/O (io), 34 I/O (io)
part D pins: 87 I/O (io), 89 I/O (io), 90 I/O (io), 91 I/O (io), 92 I/O (io), 93 I/O (io), 94 I/O (io), 95 I/O (io), 96 I/O (io), 97 I/O (io)
part E pins: 35 I/O (io), 36 I/O (io), 37 I/O (io), 39 I/O (io), 40 I/O (io), 41 I/O (io), 42 I/O (io), 43 I/O (io), 46 I/O (io), 49 I/O (io)
part F pins: 74 I/O (io), 76 I/O (io), 77 I/O (io), 78 I/O (io), 79 I/O (io), 80 I/O (io), 81 I/O (io), 82 I/O (io), 85 I/O (io), 86 I/O (io)
part G pins: 50 I/O (io), 52 I/O (io), 53 I/O (io), 54 I/O (io), 55 I/O (io), 56 I/O (io), 58 I/O (io), 59 I/O (io), 60 I/O (io), 61 I/O (io)
part H pins: 63 I/O (io), 64 I/O (io), 65 I/O (io), 66 I/O (io), 67 I/O (io), 68 I/O (io), 70 I/O (io), 71 I/O (io), 72 I/O (io), 73 I/O (io)
part I pins: 45 TDI (in), 47 TMS (in), 48 TCK (in), 83 TDO (out)
part J pins: 5 VCCINT 2.5V (power), 26 VCCIO1 (power), 38 VCCIO1 (power), 51 VCCIO1 (power), 57 VCCINT 2.5V (power), 88 VCCIO2 (power), 98 VCCINT 2.5V (power)
part K pins: 21 GND (power), 31 GND (power), 44 GND (power), 62 GND (power), 69 GND (power), 75 GND (power), 84 GND (power), 100 GND (power)

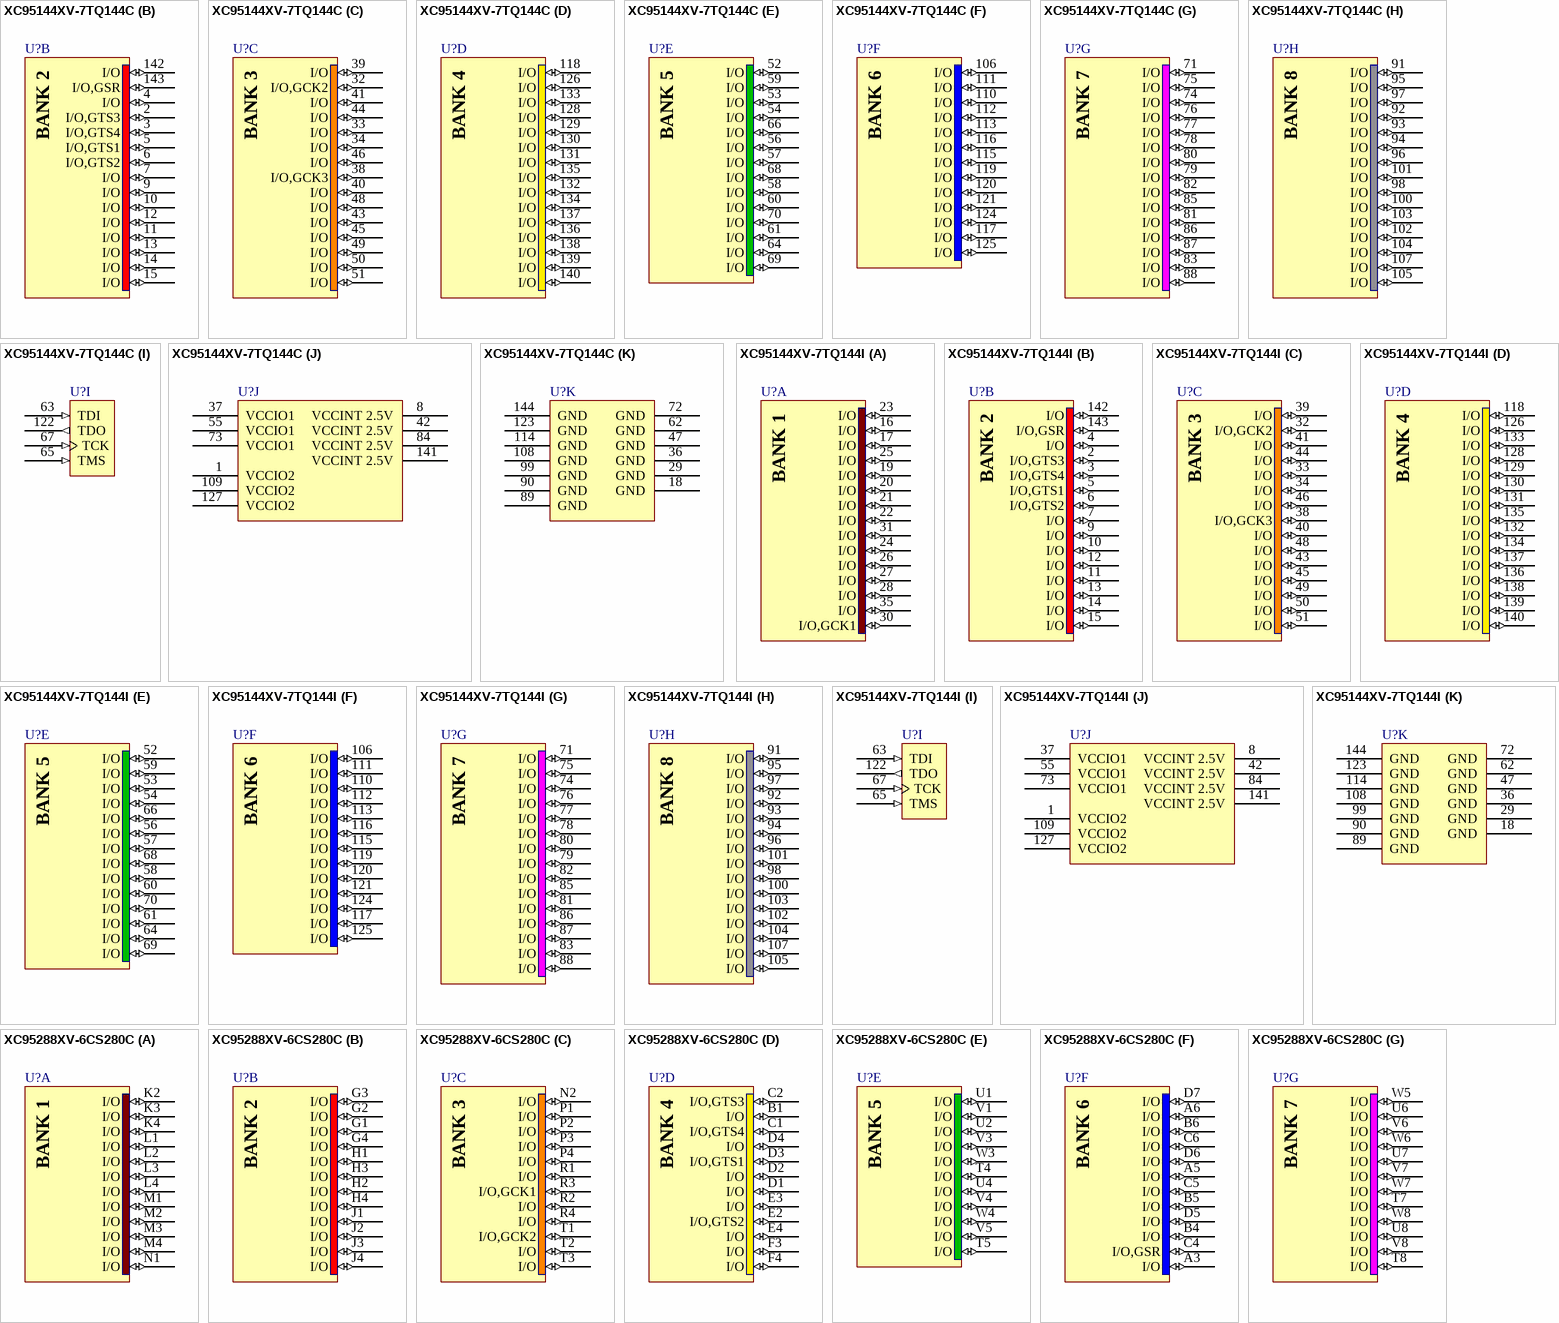
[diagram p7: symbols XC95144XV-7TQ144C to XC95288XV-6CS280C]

## XC95144XV-7TQ144C
designator U?
XC9500XV, 2.5V High-Performance 144 Macrocell CPLD, 117 User I/Os, 144-Pin TQFP, Speed Grade 7, Commercial Grade
footprint TQ144_N (Thin QFP, 144-Leads, Body 20x20mm, Pitch 0.5mm, IPC Medium Density)
footprint TQ144_L (Thin QFP, 144-Leads, Body 20x20mm, Pitch 0.5mm, IPC High Density)
footprint TQ144_M (Thin QFP, 144-Leads, Body 20x20mm, Pitch 0.5mm, IPC Low Density)
signal-integrity model XC95144XV_TQ144 (XC9500XV)
part A pins: 16 I/O (io), 17 I/O (io), 19 I/O (io), 20 I/O (io), 21 I/O (io), 22 I/O (io), 23 I/O (io), 24 I/O (io), 25 I/O (io), 26 I/O (io), 27 I/O (io), 28 I/O (io), 30 I/O,GCK1 (io), 31 I/O (io), 35 I/O (io)
part B pins: 2 I/O,GTS3 (io), 3 I/O,GTS4 (io), 4 I/O (io), 5 I/O,GTS1 (io), 6 I/O,GTS2 (io), 7 I/O (io), 9 I/O (io), 10 I/O (io), 11 I/O (io), 12 I/O (io), 13 I/O (io), 14 I/O (io), 15 I/O (io), 142 I/O (io), 143 I/O,GSR (io)
part C pins: 32 I/O,GCK2 (io), 33 I/O (io), 34 I/O (io), 38 I/O,GCK3 (io), 39 I/O (io), 40 I/O (io), 41 I/O (io), 43 I/O (io), 44 I/O (io), 45 I/O (io), 46 I/O (io), 48 I/O (io), 49 I/O (io), 50 I/O (io), 51 I/O (io)
part D pins: 118 I/O (io), 126 I/O (io), 128 I/O (io), 129 I/O (io), 130 I/O (io), 131 I/O (io), 132 I/O (io), 133 I/O (io), 134 I/O (io), 135 I/O (io), 136 I/O (io), 137 I/O (io), 138 I/O (io), 139 I/O (io), 140 I/O (io)
part E pins: 52 I/O (io), 53 I/O (io), 54 I/O (io), 56 I/O (io), 57 I/O (io), 58 I/O (io), 59 I/O (io), 60 I/O (io), 61 I/O (io), 64 I/O (io), 66 I/O (io), 68 I/O (io), 69 I/O (io), 70 I/O (io)
part F pins: 106 I/O (io), 110 I/O (io), 111 I/O (io), 112 I/O (io), 113 I/O (io), 115 I/O (io), 116 I/O (io), 117 I/O (io), 119 I/O (io), 120 I/O (io), 121 I/O (io), 124 I/O (io), 125 I/O (io)
part G pins: 71 I/O (io), 74 I/O (io), 75 I/O (io), 76 I/O (io), 77 I/O (io), 78 I/O (io), 79 I/O (io), 80 I/O (io), 81 I/O (io), 82 I/O (io), 83 I/O (io), 85 I/O (io), 86 I/O (io), 87 I/O (io), 88 I/O (io)
part H pins: 91 I/O (io), 92 I/O (io), 93 I/O (io), 94 I/O (io), 95 I/O (io), 96 I/O (io), 97 I/O (io), 98 I/O (io), 100 I/O (io), 101 I/O (io), 102 I/O (io), 103 I/O (io), 104 I/O (io), 105 I/O (io), 107 I/O (io)
part I pins: 63 TDI (in), 65 TMS (in), 67 TCK (in), 122 TDO (out)
part J pins: 1 VCCIO2 (power), 8 VCCINT 2.5V (power), 37 VCCIO1 (power), 42 VCCINT 2.5V (power), 55 VCCIO1 (power), 73 VCCIO1 (power), 84 VCCINT 2.5V (power), 109 VCCIO2 (power), 127 VCCIO2 (power), 141 VCCINT 2.5V (power)
part K pins: 18 GND (power), 29 GND (power), 36 GND (power), 47 GND (power), 62 GND (power), 72 GND (power), 89 GND (power), 90 GND (power), 99 GND (power), 108 GND (power), 114 GND (power), 123 GND (power), 144 GND (power)

## XC95144XV-7TQ144I
designator U?
XC9500XV, 2.5V High-Performance 144 Macrocell CPLD, 117 User I/Os, 144-Pin TQFP, Speed Grade 7, Industrial Grade
footprint TQ144_N (Thin QFP, 144-Leads, Body 20x20mm, Pitch 0.5mm, IPC Medium Density)
footprint TQ144_L (Thin QFP, 144-Leads, Body 20x20mm, Pitch 0.5mm, IPC High Density)
footprint TQ144_M (Thin QFP, 144-Leads, Body 20x20mm, Pitch 0.5mm, IPC Low Density)
signal-integrity model XC95144XV_TQ144 (XC9500XV)
part A pins: 16 I/O (io), 17 I/O (io), 19 I/O (io), 20 I/O (io), 21 I/O (io), 22 I/O (io), 23 I/O (io), 24 I/O (io), 25 I/O (io), 26 I/O (io), 27 I/O (io), 28 I/O (io), 30 I/O,GCK1 (io), 31 I/O (io), 35 I/O (io)
part B pins: 2 I/O,GTS3 (io), 3 I/O,GTS4 (io), 4 I/O (io), 5 I/O,GTS1 (io), 6 I/O,GTS2 (io), 7 I/O (io), 9 I/O (io), 10 I/O (io), 11 I/O (io), 12 I/O (io), 13 I/O (io), 14 I/O (io), 15 I/O (io), 142 I/O (io), 143 I/O,GSR (io)
part C pins: 32 I/O,GCK2 (io), 33 I/O (io), 34 I/O (io), 38 I/O,GCK3 (io), 39 I/O (io), 40 I/O (io), 41 I/O (io), 43 I/O (io), 44 I/O (io), 45 I/O (io), 46 I/O (io), 48 I/O (io), 49 I/O (io), 50 I/O (io), 51 I/O (io)
part D pins: 118 I/O (io), 126 I/O (io), 128 I/O (io), 129 I/O (io), 130 I/O (io), 131 I/O (io), 132 I/O (io), 133 I/O (io), 134 I/O (io), 135 I/O (io), 136 I/O (io), 137 I/O (io), 138 I/O (io), 139 I/O (io), 140 I/O (io)
part E pins: 52 I/O (io), 53 I/O (io), 54 I/O (io), 56 I/O (io), 57 I/O (io), 58 I/O (io), 59 I/O (io), 60 I/O (io), 61 I/O (io), 64 I/O (io), 66 I/O (io), 68 I/O (io), 69 I/O (io), 70 I/O (io)
part F pins: 106 I/O (io), 110 I/O (io), 111 I/O (io), 112 I/O (io), 113 I/O (io), 115 I/O (io), 116 I/O (io), 117 I/O (io), 119 I/O (io), 120 I/O (io), 121 I/O (io), 124 I/O (io), 125 I/O (io)
part G pins: 71 I/O (io), 74 I/O (io), 75 I/O (io), 76 I/O (io), 77 I/O (io), 78 I/O (io), 79 I/O (io), 80 I/O (io), 81 I/O (io), 82 I/O (io), 83 I/O (io), 85 I/O (io), 86 I/O (io), 87 I/O (io), 88 I/O (io)
part H pins: 91 I/O (io), 92 I/O (io), 93 I/O (io), 94 I/O (io), 95 I/O (io), 96 I/O (io), 97 I/O (io), 98 I/O (io), 100 I/O (io), 101 I/O (io), 102 I/O (io), 103 I/O (io), 104 I/O (io), 105 I/O (io), 107 I/O (io)
part I pins: 63 TDI (in), 65 TMS (in), 67 TCK (in), 122 TDO (out)
part J pins: 1 VCCIO2 (power), 8 VCCINT 2.5V (power), 37 VCCIO1 (power), 42 VCCINT 2.5V (power), 55 VCCIO1 (power), 73 VCCIO1 (power), 84 VCCINT 2.5V (power), 109 VCCIO2 (power), 127 VCCIO2 (power), 141 VCCINT 2.5V (power)
part K pins: 18 GND (power), 29 GND (power), 36 GND (power), 47 GND (power), 62 GND (power), 72 GND (power), 89 GND (power), 90 GND (power), 99 GND (power), 108 GND (power), 114 GND (power), 123 GND (power), 144 GND (power)

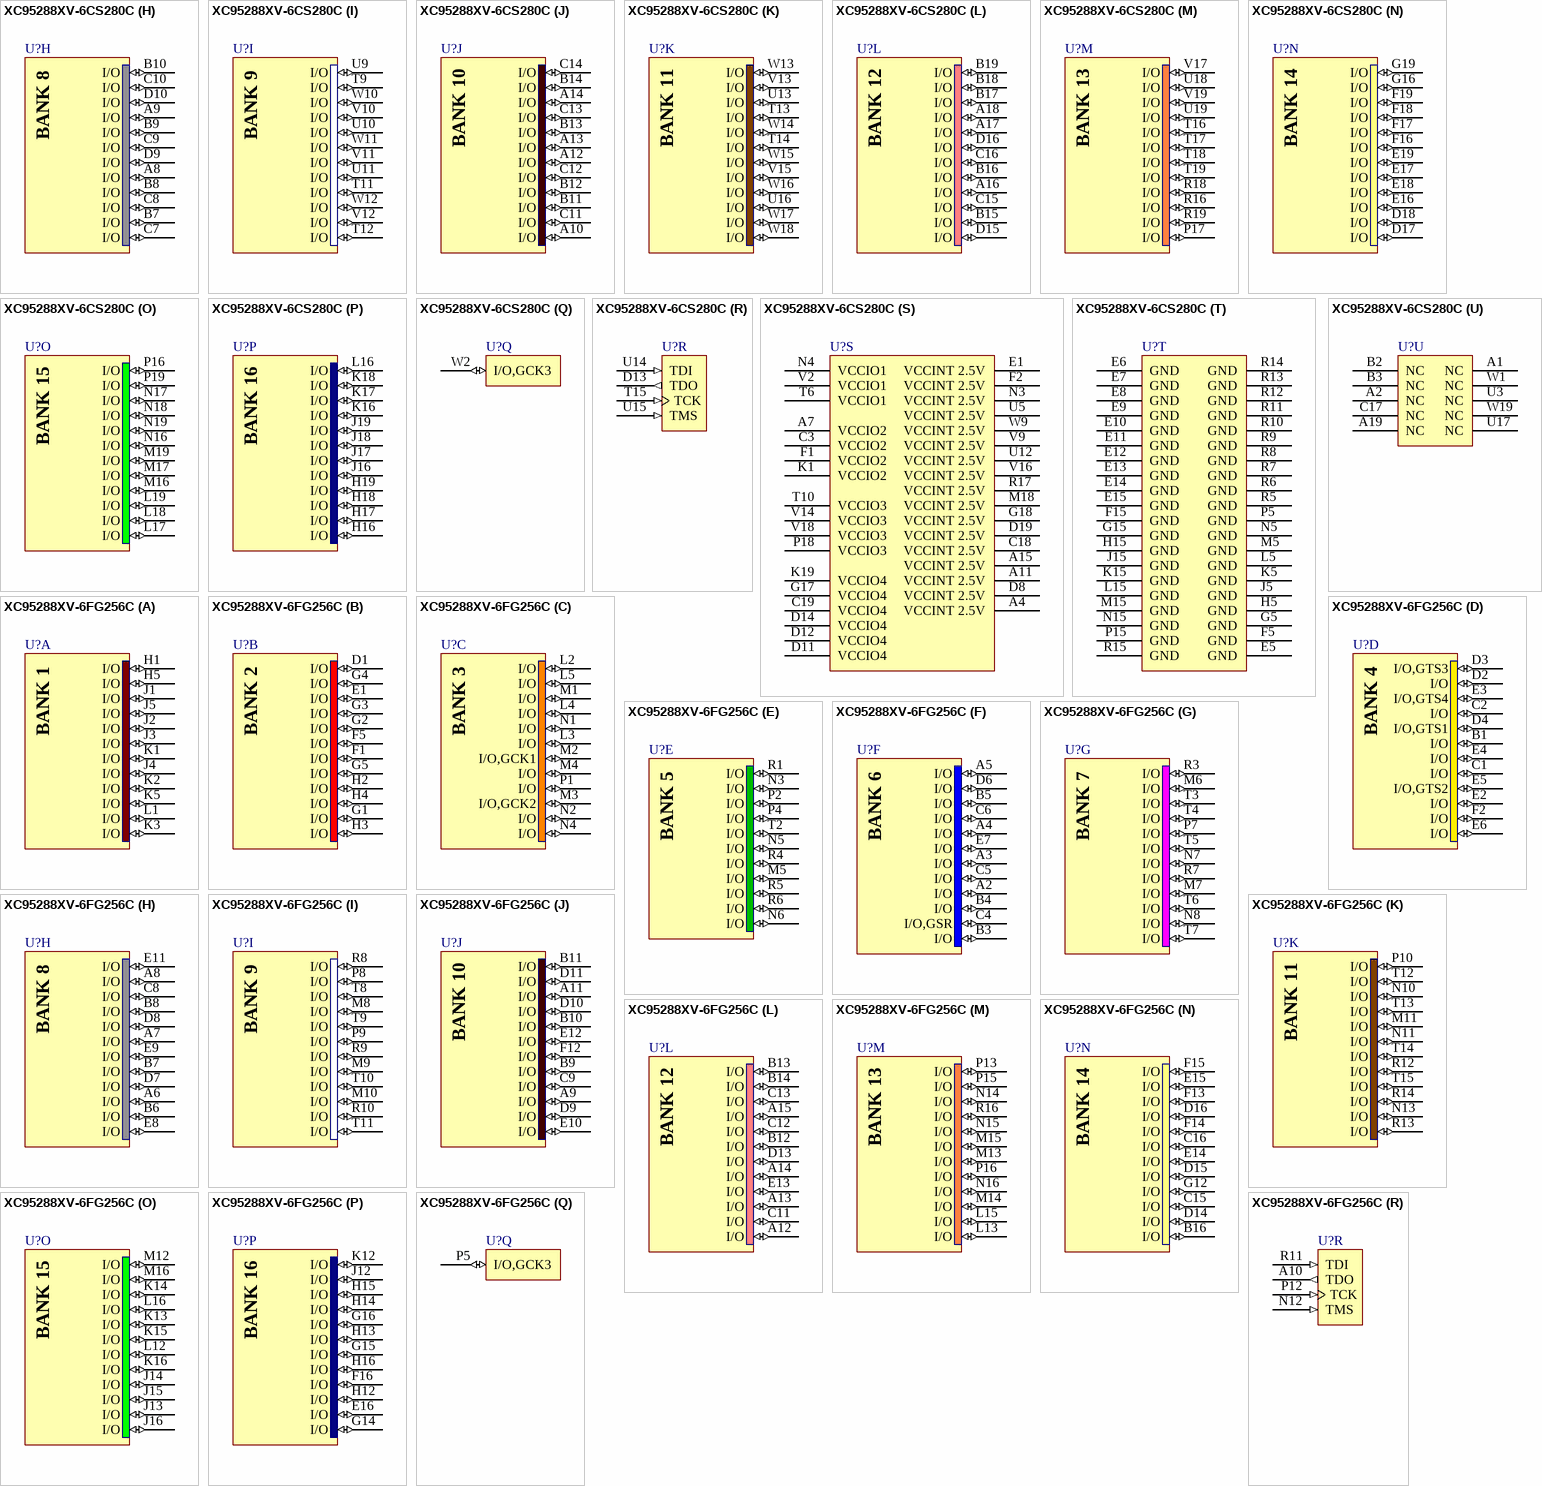
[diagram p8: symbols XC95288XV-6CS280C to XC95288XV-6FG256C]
